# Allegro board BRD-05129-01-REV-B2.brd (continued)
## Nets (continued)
GTR_DP3_C2M_N_NC: JA1.D50
GTR_DP3_C2M_P_NC: JA1.D49
GTR_DP3_M2C_N_NC: JA1.C52
GTR_DP3_M2C_P_NC: JA1.C51
GTR_REFCLK0_C2M_N_NC: JA1.C48
GTR_REFCLK0_C2M_P_NC: JA1.C47
GTR_REFCLK1_C2M_N_NC: JA1.B50
GTR_REFCLK1_C2M_P_NC: JA1.B49
GTR_REFCLK2_C2M_N: JA1.D54 R495.1 U89.5
GTR_REFCLK2_C2M_P: JA1.D53 R495.2 U89.4
GTR_REFCLK3_C2M_N_NC: JA1.A52
GTR_REFCLK3_C2M_P_NC: JA1.A51
HDA00_CC: D21.1(CATHODE) J47.2 JA1.D16 R680.2
HDA01_NC: JA1.D17
HDA02: JA1.D18 R618.1
HDA03: JA1.B16 R627.1
HDA04: JA1.B17 R633.1
HDA05: JA1.B18 R620.1
HDA06: JA1.C18 U116.11 U117.11
HDA07: JA1.C19 U116.10 U117.13
HDA08_CC: JA1.C20 Q20.1 R261.1
HDA09_NC: JA1.A15
HDA10: JA1.A16 U116.13 U117.3
HDA11: JA1.A17 R276.1
HDA12: JA1.D20 R278.1
HDA13: JA1.D21 R280.1
HDA14: JA1.D22 R282.1
HDA15: JA1.B20 R277.1
HDA16_CC: JA1.B21 R279.1
HDA17: JA1.B22 R281.1
HDA18: JA1.C22 R283.1
HDA19_NC: JA1.C23
HDA20: JA1.C24 U121.6
HDA21: JA3.C10 R579.2 U100.6
HDA22: JA3.A10 R580.2 U100.5
HPA00_CCN: JA1.C4 U109.13
HPA00_CCP_CLK: JA1.C3 U109.15
HPA01N: JA1.D8 U111.15
HPA01P: JA1.D7 U109.12
HPA02N: JA1.D5 U111.13
HPA02P: JA1.D4 U111.14
HPA03N: JA1.C7 U109.14
HPA03P: JA1.C6 U111.12
HPA04N: JA1.B5 Q31.1 R567.1 R576.2 R590.1 U99.21
HPA04P: JA1.B4 Q32.1 R575.2 R589.1 U99.26
HPA05_CCN: JA1.B2 U99.1
HPA05_CCP: JA1.B1 U99.39
HPA06N: JA1.A4 U99.3
HPA06P: JA1.A3 U99.2
HPA07N: JA1.B8 U99.37
HPA07P_CLK: JA1.B7 U99.38
HPA08N: JA1.C10 R571.2 R585.1 U99.32
HPA08P: JA1.C9 R572.2 R586.1 U99.33
HPA09N: JA1.D11 R569.2 R583.1 U99.29
HPA09P: JA1.D10 R570.2 R584.1 U99.30
HPA10_CCN: JA1.C13 R563.2 U99.24
HPA10_CCP_CLK: JA1.C12 U99.23
HPA11N: JA1.B11 U19.2
HPA11P_CLK: JA1.B10 R477.2
HPA11P_CLK_R: R477.1 U91.3
HPA12N: JA1.A10 U115.13
HPA12P_CLK: JA1.A9 U115.15
HPA13N: JA1.A13 U115.14
HPA13P: JA1.A12 U115.12
HPA14N: JA1.D14 Q23.1 R474.1
HPA14P: JA1.D13 Q22.1 R473.1
HPA15_CCN: JA3.C2 U101.1
HPA15_CCP: JA3.C1 U101.39
HPA16N: JA3.A2 U101.37
HPA16P_CLK: JA3.A1 U101.38
HPA17N: JA3.D3 R597.2 R608.1 U101.35
HPA17P: JA3.D2 Q33.1 R596.1 R605.2 R616.1 U101.21
HPA18N: JA3.B3 R600.2 R611.1 U101.32
HPA18P: JA3.B2 R603.2 R612.1 U101.33
HPA19N: JA3.C5 R598.2 R609.1 U101.29
HPA19P: JA3.C4 R599.2 R610.1 U101.30
HPA20_CCN_NC: JA3.A5
HPA20_CCP_CLK: JA3.A4 R601.2 R614.1 U101.34
HPA21N_NC: JA3.D6
HPA21P_CLK: JA3.D5 R479.2
HPA21P_CLK_R: R479.1 U91.5
HPA22N: JA3.B6 R592.2 U101.24
HPA22P: JA3.B5 U101.23
HPA23N: JA3.C8 U118.4
HPA23P_CLK: JA3.C7 U120.5
HPA24N: JA3.A8 U101.3
HPA24P: JA3.A7 U101.2
HPA25: JA3.D8 U120.4
HPA26: JA3.D9 U118.5
HPA27: JA3.B8 Q34.1 R602.2 R615.1 U101.26
HPA28: JA3.B9 U19.3
HPA_CLK0N: JA1.A7 R568.2 R582.1 U99.35
HPA_CLK0P_CLK: JA1.A6 R574.2 R588.1 U99.34
I2C_SCK_LS: R55.2 U14.9 U15.6 U16.6 U19.8 U43.38
I2C_SDA_LS: R56.2 U14.8 U15.5 U16.5 U19.7 U43.39
JTAG_TCK_C2M: J3.6 JA1.A25 R66.2 R264.1
JTAG_TDI_C2M: J3.10 JA1.A24 U22.14
JTAG_TDO_M2C: J3.8 JA1.A23 U25.4
JTAG_TMS_C2M: J3.4 JA1.A22 U25.5
JTAG_VCCO_ON: R241.1 U22.8 U24.21
LS_OE_B: Q12.3 R233.2 U22.1 U25.2
MIO24_I2C_SCK: JA1.C26 U16.3
MIO25_I2C_SDA: JA1.C27 U16.4
MIO26: J1.1 JA1.D28 R45.2
MIO27_NC: JA1.D29
MIO28_NC: JA1.D30
MIO29_NC: JA1.C30
MIO30_NC: JA1.C31
MIO31: JA1.C32 R263.1 TP37.1(TP)
MIO32_NC: JA1.A31
MIO33_NC: JA1.A32
MIO34_NC: JA1.B38
MIO35: JA1.B28 R530.2 U13.7 U19.26
MIO36: JA1.B29 U64.4
MIO37: JA1.B30 U64.5
MIO38: JA1.B32 U98.38
MIO39: JA1.B33 U98.39
MIO40: JA1.B34 U98.1
MIO41: JA1.A34 U98.2
MIO42: JA1.A35 U98.3
MIO43: JA1.A36 U98.37
MIO44: JA1.D32 R547.2 R558.1 U98.34
MIO45: JA1.D33 R545.2 R556.1 U98.33
MIO46: JA1.D34 R544.2 R555.1 U98.32
MIO47: JA1.C34 R543.2 R554.1 U98.30
MIO48: JA1.C35 R542.2 R553.1 U98.29
MIO49: JA1.C36 R541.2 R552.1 U98.35
MIO50: JA1.B36 U98.23
MIO51: JA1.B37 R536.2 U98.24
MIO52: JA1.D36 U37.1
MIO53: JA1.D37 U37.31
MIO54: JA1.D38 U37.5
MIO55: JA1.C38 U37.2
MIO56: JA1.C39 U37.3
MIO57: JA1.C40 U37.4
MIO58: JA1.B40 U37.29
MIO59: JA1.B41 U37.6
MIO60: JA1.B42 U37.7
MIO61: JA1.A38 U37.9
MIO62: JA1.A39 U37.10
MIO63: JA1.A40 U37.13
MIO64_NC: JA1.D40
MIO65_NC: JA1.D41
MIO66: JA1.D42 U94.A4 U94.B4
MIO67: JA1.C42 U94.A1 U94.B1
MIO68: JA1.C43 U94.A8 U94.B8
MIO69_NC: JA1.C44
MIO70: JA1.B44 R683.2 U95.4
MIO71: JA1.B45 R682.1 U95.2
MIO72: JA1.B46 R681.1 U95.3 U95.5
MIO73_NC: JA1.A42
MIO74_NC: JA1.A43
MIO75_NC: JA1.A44
MIO76: JA1.D44 U19.4
MIO77: JA1.D45 U19.22
MODE0_C2M: JA1.A27 R165.1 TP65.1(TP)
MODE1_C2M: JA1.A28 R164.1 TP64.1(TP)
MODE2_C2M: JA1.A29 R163.1 TP63.1(TP)
MODE3_C2M: JA1.A30 R162.1 TP62.1(TP)
MOTOR_CS_B_R: R756.2 R758.2 R760.2 U109.7
MOTOR_PA_CRNT: C723.1 J52.1(P1) R61.1 R646.2
MOTOR_PA_CS_B: R756.1 U108.10
MOTOR_PA_CURRENT+: C813.1 R740.2 U108.8
MOTOR_PA_CURRENT-: C812.1 R741.2 U108.7(VINB-)
MOTOR_PA_DATAA: U108.14 U109.8
MOTOR_PA_DATAB: U108.13 U109.9
MOTOR_PA_HS: C688.2 J27.1(P1) Q35.1 Q35.2 Q35.3(S3) Q36.5 R638.1 U102.4 U105.8
MOTOR_PA_I: R646.1 U105.5
MOTOR_PA_OUT: J32.1 R638.2 R641.1 U105.1
MOTOR_PA_R_V+: R702.2 R738.1 U127.4
MOTOR_PA_R_V-: R703.2 R739.1 U127.5
MOTOR_PA_SCLK: R755.1 U108.15
MOTOR_PA_VOCM: C711.1 U105.3 U105.7 U123.6 U123.7(OUT) U127.2(VOCM) U128.2(VOCM)
MOTOR_PA_VOCM2: R58.1 R63.1 U123.1 U123.2
MOTOR_PA_VOLT: R64.1 U135.1 U135.2
MOTOR_PA_VOLTAGE+: C811.1 R738.2 U108.1
MOTOR_PA_VOLTAGE-: C810.1 R739.2 U108.2
MOTOR_PB_CRNT: C734.1 J53.1(P1) R650.2 R712.1
MOTOR_PB_CS_B: R758.1 U110.10
MOTOR_PB_CURRENT+: C817.1 R744.2 U110.8
MOTOR_PB_CURRENT-: C816.1 R745.2 U110.7(VINB-)
MOTOR_PB_DATAA: U110.14 U111.6
MOTOR_PB_DATAB: U110.13 U111.7
MOTOR_PB_HS: C696.2 J29.1(P1) Q38.1 Q38.2 Q38.3(S3) Q39.5 R639.1 U103.4 U106.8
MOTOR_PB_I: R650.1 U106.5
MOTOR_PB_OUT: J32.2 R639.2 R647.1 U106.1
MOTOR_PB_SCLK: R757.1 U110.15
MOTOR_PB_VOCM: C713.1 U106.3 U106.7 U124.6 U124.7(OUT) U129.2(VOCM) U130.2(VOCM)
MOTOR_PB_VOCM2: R707.1 R711.1 U124.1 U124.2
MOTOR_PB_VOLT: R708.1 U136.6 U136.7(OUT)
MOTOR_PB_VOLTAGE+: C815.1 R742.2 U110.1
MOTOR_PB_VOLTAGE-: C814.1 R743.2 U110.2
MOTOR_PC_CRNT: C743.1 J54.1(P1) R656.2 R720.1
MOTOR_PC_CS_B: R760.1 U112.10
MOTOR_PC_CURRENT+: C821.1 R748.2 U112.8
MOTOR_PC_CURRENT-: C820.1 R749.2 U112.7(VINB-)
MOTOR_PC_DATAA: U111.8 U112.14
MOTOR_PC_DATAB: U111.9 U112.13
MOTOR_PC_HS: C703.2 J31.1(P1) Q40.1 Q40.2 Q40.3(S3) Q41.5 R640.1 U104.4 U107.8
MOTOR_PC_I: R656.1 U107.5
MOTOR_PC_OUT: J32.3 R640.2 R651.1 U107.1
MOTOR_PC_SCLK: R759.1 U112.15
MOTOR_PC_VOCM: C715.1 U107.3 U107.7 U125.6 U125.7(OUT) U131.2(VOCM) U132.2(VOCM)
MOTOR_PC_VOCM2: R715.1 R719.1 U125.1 U125.2
MOTOR_PC_VOLT: R716.1 U136.1 U136.2
MOTOR_PC_VOLTAGE+: C819.1 R746.2 U112.1
MOTOR_PC_VOLTAGE-: C818.1 R747.2 U112.2
MOTOR_SCLK_R: R755.2 R757.2 R759.2 U109.6
MP5016_DVDT: C206.1 U41.10
MP5016_EN: R133.2 U41.9
MP5016_GATE: C234.1 Q5.3 U41.8
MP5016_ILIMIT: R135.1 U41.4
MP5016_MODE: C235.1 R134.1 U41.5
OSC_25M_CLK: R501.2 U91.1
OSC_25M_CLK_R: R501.1 U92.3
OSC_25M_OE: R500.2 U92.1
OSC_26M_OE: R494.2 U89.1
PA_HB: C688.1 D3.1(CATHODE) U102.2
PA_HO: R619.1 U102.3
PA_HOG: Q35.4 R619.2
PA_LO: R621.1 U102.10
PA_LOG: Q36.4 R621.2
PA_RDT: R625.1 U102.6
PB_HB: C696.1 D4.1(CATHODE) U103.2
PB_HO: R628.1 U103.3
PB_HOG: Q38.4 R628.2
PB_LO: R629.1 U103.10
PB_LOG: Q39.4 R629.2
PB_RDT: R631.1 U103.6
PC4_CON_PGND: J3.13 Q12.1 Q13.3 R234.2
PC_HB: C703.1 D5.1(CATHODE) U104.2
PC_HO: R634.1 U104.3
PC_HOG: Q40.4 R634.2
PC_LO: R635.1 U104.10
PC_LOG: Q41.4 R635.2
PC_RDT: R637.1 U104.6
PL_1V8: C7.1 C8.1 C582.1 C591.1 C592.1 C645.1 C646.1 C647.1 C654.1 C655.1 C656.1 C657.1 C667.1 C668.1 C669.1 C676.1 C677.1 C678.1 C679.1 C719.1 C733.1 C755.1 C769.1 C778.1 JA1.D1 JA1.D2 R14.1 R446.1 R500.1 R507.1 R563.1 R564.1 R568.1 R569.1 R570.1 R571.1 R572.1 R573.1 R574.1 R575.1 R592.1 R593.1 R597.1 R598.1 R599.1 R600.1 R601.1 R602.1 R603.1 R604.1 TP10.1(TP) TP56.1(TP) U3.5-6 U3.12 U91.6 U92.4(VDD) U99.25 U99.31 U99.40 U101.25 U101.31 U101.40 U109.2(VCCB) U111.2(VCCB) U115.2(VCCB) U118.6(VCCB) U120.6(VCCB)
PL_1V8_FB: R14.2 R16.1 U3.10
PL_2V5: C21.1 C22.1 C716.1 C717.1 C727.1 C728.1 C740.1 C741.1 C752.1 C753.1 R24.1 TP11.1(TP) TP57.1(TP) U9.1 U108.9 U110.9 U112.9 U114.9
PL_2V5_EN: C829.1 R472.2 U9.5
PL_2V5_FB: C21.2 R23.1 R24.2 U9.4
PL_3V3: C23.1 C29.1 C237.1 C581.1 C614.1 C615.1 C666.1 C710.1 C712.1 C714.1 C718.1 C720.1 C721.1 C729.1 C730.1 C732.1 C738.1 C739.1 C747.1 C754.1 C756.1 C757.1 C764.1 C766.1 C768.1 C773.1 C777.1 C785.1 C789.1 C793.1 C794.1 C795.1 C796.1 C797.1 C798.1 C799.1 C800.1 C801.1 C802.1 C803.1 C804.1 C805.1 J25.P11_L2_U J25.P11_L4_L J25.P14_L1_U J25.P14_L3_L J47.1 JA1.B13 JA1.B14 L16.1 L17.1 R166.1 R471.1 R472.1 R524.1 R565.1 R576.1 R579.1 R580.1 R594.1 R605.1 R622.1 R672.1 R680.1 TP12.1(TP) TP58.1(TP) U8.8 U9.8 U42.5 U97.5-6 U97.12 U100.2 U100.8 U105.6(VS) U106.6(VS) U107.6(VS) U108.16 U109.3 U109.5 U110.16 U111.3 U111.4 U111.5 U112.16 U113.6(VS) U114.16 U115.3 U115.5 U116.14(VCCB) U117.6 U117.16(VCC) U118.7 U118.10 U119.14 U120.7 U123.8 U124.8 U125.8 U127.3 U127.7 U128.3 U128.7 U129.3 U129.7 U130.3 U130.7 U131.3 U131.7 U132.3 U132.7 U133.3 U133.7 U134.3 U134.7 U135.8 U136.8 U137.8
PL_3V3_FB: R524.2 R525.1 U97.10
PL_4V5_TRQ: C770.1 C771.1 C772.1 C780.1 C787.1 C788.1 J45.1 R673.1 R684.1 TP13.1(TP) TP59.1(TP) U119.13 U122.1
PL_4V5_TRQ_FB: C788.2 R684.2 R685.1 U122.4
PL_5V0: C618.1 C763.1 C765.1 C767.1 J42.4 J43.7 J43.8 Q25.3 R664.1 R665.1 R666.1 R667.1 TP14.1(TP) TP60.1(TP) U116.1
PL_12V0: C617.1 C692.1 C693.1 C700.1 C701.1 C707.1 C708.1 C783.1 Q24.3 R617.1 R626.1 R632.1 TP15.1(TP) TP61.1(TP) U102.1 U103.1 U104.1 U121.4(VDD)
PL_ETH_0V9: C27.1 C28.1 C650.1 C651.1 C652.1 C653.1 C661.1 C662.1 C663.1 C672.1 C673.1 C674.1 C675.1 C683.1 C684.1 C685.1 R27.1 TP9.1(TP) TP55.1(TP) U8.1 U99.4 U99.28 U99.36 U101.4 U101.28 U101.36
PL_ETH_0V9_EN: C828.1 R471.2 U8.5
PL_ETH_0V9_FB: C27.2 R27.2 R29.1 U8.4
PL_GEM1_LED1_LS: J25.P13_L1_U R577.2
PL_GEM1_LED2_LS: J25.P12_L2_U R578.2
PL_GEM1_MDI_0_N: J25.P1_U U99.13
PL_GEM1_MDI_0_P: J25.P2_U U99.12
PL_GEM1_MDI_1_N: J25.P3_U U99.15
PL_GEM1_MDI_1_P: J25.P4_U U99.14
PL_GEM1_MDI_2_N: J25.P5_U U99.17
PL_GEM1_MDI_2_P: J25.P6_U U99.16
PL_GEM1_MDI_3_N: J25.P7_U U99.19
PL_GEM1_MDI_3_P: J25.P8_U U99.18
PL_GEM1_MDIX_MODE: R573.2 R587.1 U99.27
PL_GEM1_RESET_B: R565.2 U19.12 U99.7
PL_GEM2_LED3_LS: J25.P13_L3_L R606.2
PL_GEM2_LED4_LS: J25.P12_L4_L R607.2
PL_GEM2_MDI_0_N: J25.P1_L U101.13
PL_GEM2_MDI_0_P: J25.P2_L U101.12
PL_GEM2_MDI_1_N: J25.P3_L U101.15
PL_GEM2_MDI_1_P: J25.P4_L U101.14
PL_GEM2_MDI_2_N: J25.P5_L U101.17
PL_GEM2_MDI_2_P: J25.P6_L U101.16
PL_GEM2_MDI_3_N: J25.P7_L U101.19
PL_GEM2_MDI_3_P: J25.P8_L U101.18
PL_GEM2_MDIX_MODE: R604.2 R613.1 U101.27
PL_GEM2_RESET_B: R594.2 U19.13 U101.7
PL_RESET_OUT3_B_NC: U19.17
PMOD1_IO1_HDA11: C372.1 J2.1 R274.2 R276.2
PMOD1_IO2_HDA12: C374.1 J2.3 R278.2
PMOD1_IO3_HDA13: C377.1 J2.5 R280.2
PMOD1_IO4_HDA14: C379.1 J2.7 R282.2
PMOD1_IO5_HDA15: C373.1 J2.2 R275.2 R277.2
PMOD1_IO6_HDA16_CC: C375.1 J2.4 R279.2
PMOD1_IO7_HDA17: C378.1 J2.6 R281.2
PMOD1_IO8_HDA18: C380.1 J2.8 R283.2
PMOD_3V3: C238.1 C376.1 C387.1 J2.11 J2.12 U42.1(OUT)
PMOD_PWR_EN: R167.1 U42.4
PMOD_PWR_FLT_B: R166.2 U42.3
PMU_RESET_OUT_B: J51.2(P2) U19.16
PS_1V2: C24.1 C25.1 C283.1 C284.1 C285.1 C286.1 C289.1 C290.1 C291.1 C292.1 C295.1 C296.1 R21.1 TP5.1(TP) TP51.1(TP) U5.5-6 U5.12 U43.5 U43.12 U43.15 U43.21 U43.28 U43.33 U43.43 U43.49
PS_1V2_FB: R21.2 R26.1 U5.10
PS_1V8: C50.1 C81.1 C91.1 C92.1 C275.1 C276.1 C277.1 C329.1 C600.1 C612.1 C613.1 C622.1 C623.1 C624.1 C631.1 C632.1 C633.1 C640.1 J3.2 L10.1 R45.1 R46.1 R47.1 R48.1 R49.1 R210.1 R447.1 R448.1 R449.1 R450.1 R451.1 R515.1 R516.1 R522.1 R530.1 R536.1 R537.1 R541.1 R542.1 R543.1 R544.1 R545.1 R546.1 R547.1 R548.1 R683.1 TP6.1(TP) TP52.1(TP) U13.1 U13.10 U16.2 U22.2(VCCB) U22.12 U22.13 U25.6(VCCB) U37.8 U37.11 U37.14 U37.28 U37.30 U37.32 U64.6(VCCB) U94.A5 U94.B5 U96.1 U98.25 U98.31 U98.40
PS_1V8_EN: R521.2 U96.5
PS_1V8_FB: C612.2 R522.2 R523.1 U96.4
PS_1V8_RS485: C602.1 L10.2 R519.1 U95.1
PS_3V3: C1.1 C2.1 C5.1 C17.1 C53.1 C64.1 C176.1 C297.1 C298.1 C299.1 C300.1 C303.1 C304.1 C559.1 C560.1 C561.1 C574.1 C589.1 C611.1 J24.11 J24.13 L15.1 R1.1 R54.1 R55.1 R56.1 R130.1 R218.1 R220.2 R243.1 R256.2 R429.1 R463.1 R464.1 R468.2 R469.2 R494.1 R521.1 R538.1 R549.1 TP7.1(TP) TP53.1(TP) U1.7-9 U12.8 U15.1 U15.8 U38.6 U38.14 U38.22 U38.36 U43.16 U43.31 U43.37 U43.44 U43.55 U89.6(VCC) U96.8
PS_3V3_FB: R1.2 R2.1 U1.10
PS_3V3_MODE: R4.2 R5.1 U1.13
PS_3V3_RAMP: C5.2 U1.11
PS_ERROR_OUT_M2C: JA1.B24 TP38.1(TP)
PS_ERROR_STATUS_M2C: JA1.B25 TP39.1(TP)
PS_ETH_0V9: C14.1 C16.1 C627.1 C628.1 C629.1 C630.1 C636.1 C637.1 C638.1 R6.1 TP8.1(TP) TP54.1(TP) U12.1 U98.4 U98.28 U98.36
PS_ETH_0V9_EN: R243.2 U12.5
PS_ETH_0V9_FB: C14.2 R6.2 R17.1 U12.4
PS_GEM0_LED0_CA: J24.12 R561.2
PS_GEM0_LED1_CA: J24.14(YLW_CA) R551.2
PS_GEM0_MDI_0_N: J24.2 U98.13
PS_GEM0_MDI_0_P: J24.1 U98.12
PS_GEM0_MDI_1_N: J24.6 U98.15
PS_GEM0_MDI_1_P: J24.3 U98.14
PS_GEM0_MDI_2_N: J24.5 U98.17
PS_GEM0_MDI_2_P: J24.4 U98.16
PS_GEM0_MDI_3_N: J24.8 U98.19
PS_GEM0_MDI_3_P: J24.7 U98.18
PS_GEM0_MDIX_MODE: R546.2 R557.1 U98.27
PS_GEM0_PHY_CFG0: Q29.1 R549.2 R550.1 R560.1 U98.21
PS_GEM0_PHY_CFG1: Q30.1 R548.2 R559.1 U98.26
PS_GEM0_RESET_B: R538.2 U19.29 U98.7
PS_GEM0_XTAL_IN: C644.1 R540.2 U98.9 X14.3(X3)
PS_GEM0_XTAL_OUT: C643.1 R540.1 U98.8(XTAL_O) X14.1
PS_POR_B: J51.1 JA1.C15 Q45.3 U19.11
PS_RESET_OUT2_B_NC: U19.19
PS_RESET_OUT5_B_NC: U19.32
PS_RESET_OUT6_B_NC: U19.10
PS_SRST_C2M_B: J1.3(P3) J3.14 JA1.C16 Q47.3
PWRGD_FPD_M2C: JA1.D24 Q7.1
PWRGD_LPD_M2C: JA1.D25 Q17.1
PWRGD_PL_M2C: JA1.D26 Q9.1
PWROFF_C2M_B: C207.1 J12.3(PLUG DET) JA1.B26 Q6.1 Q21.3 U7.3(PG)
QEI_DP_A_N: D18.2(CATHODE2) J43.5 R669.2 U117.9
QEI_DP_A_P: D18.1 J43.6 R669.1 U117.10
QEI_DP_B_N: D17.2(CATHODE2) J43.9(P9) R670.2 U117.15
QEI_DP_B_P: D17.1 J43.10 R670.1 U117.14
QEI_DP_I_N: D19.2(CATHODE2) J43.3 R671.2 U117.1
QEI_DP_I_P: D19.1 J43.4 R671.1 U117.2
QEI_LOW_REF: R667.2 R668.1 U117.7
QEI_SE_A: D16.2(CATHODE2) J42.3 R665.2 U116.4
QEI_SE_B: D15.2(CATHODE2) J42.5 R666.2 U116.5
QEI_SE_I: D16.1 J42.2 R664.2 U116.2
QEI_SEL: J44.1 R672.2 U116.8 U117.12
SD_CTRLR_RESET_B: R429.2 U19.18 U38.18
SDIO_CD_B: J11.13 R130.2 U38.26
SDIO_CLK: R249.1 U38.9
SDIO_CLK_R: J11.5 R249.2 U82.7
SDIO_CMD: R248.1 U38.11
SDIO_CMD_R: J11.3 R248.2 U82.6
SDIO_DATA0: R250.1 U38.5
SDIO_DATA0_R: J11.7 R250.2 U82.1
SDIO_DATA1: R251.1 U38.4
SDIO_DATA1_R: J11.8 R251.2 U82.2
SDIO_DATA2: R252.1 U38.25
SDIO_DATA2_R: J11.1 R252.2 U82.3
SDIO_DATA3: R253.1 U38.23
SDIO_DATA3_R: J11.2 R253.2 U82.5
SDIO_SCK: R464.2 U38.31
SDIO_SDA: R463.2 U38.27
SDIO_VDD: C369.1 C557.1 C558.1 C565.1 J11.4 R462.1 U38.21 U82.8(VCC)
SDIO_VDD18: C175.1 U38.13
SDIO_VDD18PLL: C562.1 U38.34
SDIO_WP: R465.1 U38.30
SDIO_XTAL1: C563.1 R466.1 U38.33 X11.3(X3)
SDIO_XTAL2: C564.1 R466.2 U38.32(XTAL2) X11.1
SOM240_1_C45_NC: JA1.C45
SOM240_1_D46_NC: JA1.D46
SOM_5V0: C323.1 C324.1 C353.1 C354.1 JA1.A59 JA1.A60 JA1.B60 JA1.C59 JA1.C60 JA1.D60 U14.14 U14.15 U14.16
TRQ_CS_B: U119.3 U120.9
TRQ_REFIN_N: C774.2 C776.1 R674.2 R675.2 U119.10
TRQ_REFIN_P: C774.1 C775.1 R673.2 R674.1 U119.9
TRQ_SCLK: U119.1(SCLK) U120.8
TRQ_SDI: U118.9 U119.16
TRQ_SDO: U118.8 U119.15
TRQ_SNS_N: D20.2(CATHODE2) J45.4(P4) R677.1
TRQ_SNS_P: D20.1 J45.3 R676.1
TRQ_SNS_R_N: C779.2 C782.1 R677.2 U119.6
TRQ_SNS_R_P: C779.1 C781.1 R676.2 U119.5
TS_CLK: TP40.1(TP) U119.2
USB0_ATEST: R222.1 U43.52
USB0_CFG_BC_EN: R219.1 U43.40
USB0_CFG_NON_REM: R220.1 U43.41
USB0_D1_N: U38.3 U43.2
USB0_D1_P: U38.2 U43.1
USB0_D2_N: U43.9 U44.11 X6.1
USB0_D2_P: U43.8 U44.12 X6.2
USB0_D3_N: U43.18 U44.2 X5.1
USB0_D3_P: U43.17 U44.3 X5.2
USB0_HUB_RESET_B: R218.2 U19.1 U43.42
USB0_PHY_RESET_B: R210.2 U19.28 U37.27
USB0_PRT_CTL1_NC: U43.36
USB0_PRT_CTL2: U43.35 U45.3 U45.8
USB0_PRT_CTL3: U43.34 U45.4 U45.5
USB0_RBIAS: R221.1 U43.56
USB0_SSRX2_N: U43.14 U44.14 U66.1 U66.10(NC4)
USB0_SSRX2_P: U43.13 U44.15 U66.2 U66.9
USB0_SSRX3_N: U43.23 U44.5 U66.4 U66.7
USB0_SSRX3_P: U43.22 U44.6 U66.5 U66.6
USB0_SSTX2_C_N: C280.1 U44.17 U67.4 U67.7
USB0_SSTX2_C_P: C282.1 U44.18 U67.5 U67.6
USB0_SSTX2_N: C280.2 U43.11
USB0_SSTX2_P: C282.2 U43.10
USB0_SSTX3_C_N: C279.2 U44.8 U67.1 U67.10(NC4)
USB0_SSTX3_C_P: C281.2 U44.9 U67.2 U67.9
USB0_SSTX3_N: C279.1 U43.20
USB0_SSTX3_P: C281.1 U43.19
USB0_USB3320_D_N: U37.19 U43.46
USB0_USB3320_D_P: U37.18 U43.45
USB0_VBUS2: C274.1 U44.10(U_VBUS) U45.7 X6.6(VBUS)
USB0_VBUS3: C272.1 U44.1 U45.6(OUT2) X5.6(VBUS)
USB_JTAG_DM_N: J4.2 U24.7 X1.2
USB_JTAG_DM_P: J4.3 U24.8 X1.1
USB_JTAG_FLTR: C78.1 C87.1 C89.1 L4.1 R40.1 U11.5 U11.8
USB_JTAG_VBUS: C88.1 J4.1(VBUS) L4.2 X1.6(VBUS)
USB_JTAG_VCORE: C95.1 C96.1 C97.1 C98.1 U24.12 U24.37 U24.49(VREGOUT) U24.64
USB_JTAG_VPHY: C82.1 C83.1 L2.2 U24.4
USB_JTAG_VPLL: C84.1 C85.1 L3.2 U24.9
USB_PWRD_VCCIO: C44.1 C79.1 C80.1 C90.1 C93.1 C94.1 C99.1 C100.1 C101.1 C102.1 C105.1 D24.1(CATHODE) D25.1(CATHODE) L2.1 L3.1 R36.1 R74.1 R75.1 R76.1 R77.1 R233.1 R234.1 R235.1 R266.1 R267.1 R764.1 R765.1 U11.1 U22.3 U22.4 U24.20 U24.31 U24.42 U24.50 U24.56 U25.7 U25.10 U26.8 U64.7 U64.10
UTIL_3V3: C41.1 C42.1 C49.1 DS1.2 DS2.2 DS3.2 DS4.2 DS5.2 DS6.2 DS7.2 DS8.2 DS9.2 R39.1 R260.1 TP4.1(TP) TP50.1(TP) U7.1 U14.10(VS)
VISOIN_RS485: C603.1 C604.1 L12.2 U95.16
VISOOUT_RS485: C608.1 C609.1 C610.1 L12.1 R534.2 U95.12
VREF_DCLINK: C760.1 C761.1 C762.1 R736.2 U114.3 U114.6
VREF_PA: C724.1 C725.1 C726.1 R730.2 U108.3 U108.6
VREF_PA_R: C806.1 R730.1 R731.2 U123.3 U123.5
VREF_PB: C735.1 C736.1 C737.1 R732.2 U110.3 U110.6
VREF_PB_R: C807.1 R732.1 R733.2 U124.3 U124.5
VREF_PC: C744.1 C745.1 C746.1 R734.2 U112.3 U112.6
VREF_PC_R: C808.1 R734.1 R735.2 U125.3 U125.5
WATCHDOG_CRST: C52.1 R49.2 U13.4
WATCHDOG_CWD: C51.1 R48.2 U13.2
WATCHDOG_SET0: R47.2 R51.1 U13.3
WATCHDOG_SET1: R46.2 R50.1 U13.6
WATCHDOG_WDO_B: J1.2 U13.8(WDO_B)
Y_RS485: D23.2(CATHODE2) J22.4(P4) U95.17
Z_RS485: D23.1 J22.3 U95.18(Z)
N1366089: C208.2 D2.2 L9.2 Q18.3
N1766802: R33.1 U6.2
N1766806: C37.1 R33.2
N1766990: Q21.2(SOURCE) R265.2 U6.7
N1767106: C39.2 R30.2 R31.1 R32.2
N1767370: C319.2 R223.1
N2390901: Q18.1 Q20.3 R260.2
N2549814: C344.1 R264.2
N3548094: R428.1 U38.35
N3957555: R213.1 U37.24
N3957585: R209.2 U37.22
N3957595: C278.2 U37.20
N3957977: C568.1 U43.54 X13.1
N3957979: C569.1 U43.53(XTALO) X13.3(X2)
N3958007: R468.1 U43.24
N3958011: R469.1 U43.25
N3958031: C566.1 R467.1 U37.26 X12.3(X3)
N3958033: C567.1 R467.2 U37.25(XO) X12.1
N5304511: C642.1 J24.9
N5304817: R537.2 U98.22
N5305693: Q30.3 R561.1
N5305711: R539.1 U98.10
N5322338: C665.1 J25.P9_U(TRCT1/2/3/4_U)
N5322486: R564.2 U99.22
N5323316: R566.1 U99.10
N5323550: Q32.3 R578.1
N5323954: Q31.3 R567.2 R577.1
N5327477: C687.1 J25.P9_L
N5327617: R593.2 U101.22
N5328445: R595.1 U101.10
N5328687: Q34.3 R607.1
N5371142: Q29.3 R550.2 R551.1
N5372640: Q33.3 R596.2 R606.1
N5400806: J21.2 R520.1
N5403476: J19.2 R517.1
N5403484: J20.2 R518.1
N5403540: C601.1 R517.2 R518.2
N15688918: DS10.2 R622.2
N15743132: R581.1 U100.7(WC_B)
N15988053: Q28.1 R531.2 R532.1
N15988135: Q28.3 R533.1
N15988139: DS9.1 R533.2
N15991161: J23.1 R164.2
N15992386: J40.1(P1) Q44.3 R660.2 R661.1 R662.1
N15992390: J41.1(P1) R663.1 U113.5
N15992479: C695.1 J26.1(P1) R618.2 R624.1 U102.8
N15992497: C702.1 J28.1(P1) R627.2 R630.1 U103.8
N15992515: C709.1 J30.1(P1) R633.2 R636.1 U104.8
N16064973: R526.2 R528.1 R754.1
N16065039: C619.1 Q24.1 R528.2
N16065865: Q27.3 R527.2 R529.1
N16065931: C620.1 Q25.1 R529.2
N16074030: R451.2 U19.5
N16074034: R450.2 U19.6
N16074038: R449.2 U19.9
N16074042: R448.2 U19.20
N16074046: R447.2 U19.21
N16074090: R446.2 U19.27
N16074170: R507.2 U91.2
N16074248: C73.1 R54.2 U16.7(VREF2) U16.8
N16077585: Q22.3 R294.1
N16077589: DS7.1 R294.2
N16077723: Q23.3 R295.1
N16077727: DS8.1 R295.2
N16080552: Q6.3 R157.1
N16080556: DS1.1 R157.2
N16080656: Q17.3 R254.1
N16080660: DS6.1 R254.2
N16080760: Q7.3 R158.1
N16080764: DS2.1 R158.2
N16080864: Q8.3 R159.1
N16080868: DS3.1 R159.2
N16080968: Q9.3 R160.1
N16080972: DS4.1 R160.2
N16081072: Q10.3 R161.1
N16081076: DS5.1 R161.2
N16081750: R66.1 U22.15
N16081820: J4.4 X1.3
N16081954: C88.2 J4.5 L5.2
N16082016: R75.2 U24.14
N16082024: R74.2 R78.1 U26.4
N16082026: R76.2 U24.62 U26.2
N16082028: R77.2 U24.63 U26.1
N16082050: R78.2 U24.61 U26.3
N16082060: C103.1 U24.2 X2.1
N16082074: C104.1 U24.3 X2.3(X3)
N16082098: R79.2 U24.6
N16087534: C370.1 R274.1
N16087546: C371.1 R275.1
N16095299: R534.1 U95.13
N16189579: D3.2 R617.2
N16189629: D4.2 R626.2
N16189705: D5.2 R632.2
N16192308: C694.1 Q37.1 R620.2 R623.1 U102.7 U103.7 U104.7
N16238907: R519.2 U95.8
N17003721: R641.2 R642.1 R643.1 TP41.1(TP)
N17003765: C722.1 R643.2 U135.3
N17003879: R647.2 R648.1 R649.1 TP43.1(TP)
N17003923: C731.1 R649.2 U136.5
N17004020: R651.2 R652.1 R653.1 TP45.1(TP)
N17004081: C742.1 R653.2 U136.3
N17015726: R63.2 R702.1 U127.1
N17015844: R64.2 R703.1 U127.8
N17015909: R58.2 R704.1 U128.1
N17015913: R704.2 R740.1 U128.4
N17016027: R61.2 R705.1 U128.8
N17016033: R705.2 R741.1 U128.5
N17019057: R706.1 R707.2 U129.1
N17019061: R706.2 R742.1 U129.4
N17019189: R708.2 R709.1 U129.8
N17019195: R709.2 R743.1 U129.5
N17019244: R710.1 R711.2 U130.1
N17019248: R710.2 R744.1 U130.4
N17019376: R712.2 R713.1 U130.8
N17019382: R713.2 R745.1 U130.5
N17020691: R714.1 R715.2 U131.1
N17020695: R714.2 R746.1 U131.4
N17020826: R716.2 R717.1 U131.8
N17020832: R717.2 R747.1 U131.5
N17020881: R718.1 R719.2 U132.1
N17020885: R718.2 R748.1 U132.4
N17021016: R720.2 R721.1 U132.8
N17021022: R721.2 R749.1 U132.5
N17021071: R722.1 R723.2 U133.1
N17021075: R722.2 R750.1 U133.4
N17021203: R724.2 R725.1 U133.8
N17021209: R725.2 R751.1 U133.5
N17021264: R726.1 R727.2 U134.1
N17021268: R726.2 R752.1 U134.4
N17021396: R728.2 R729.1 U134.8
N17021402: R729.2 R753.1 U134.5
N17049267: C758.1 R662.2 U135.5
N17065894: C809.1 R736.1 R737.2 U137.3 U137.5
N17098770: DS10.1 Q37.3
N17140493: Q26.3 R754.2
N17244604: Q43.3 Q44.1 R762.2 R763.1
N17444223: C826.1 D24.2 Q45.1 Q46.3 R267.2
N17444428: C827.1 D25.2 Q47.1 Q48.3 R764.2

Pads without a net: D15 1; F1 2 4; J3 12; J19 3; J20 3; J21 3; J44 3; U1 4-6 16 19 20; U3 3-4; U5 3-4; U6 1 15; U7 2 7; U8 2 7; U9 2 7; U11 2 7; U12 2 7; U13 9; U14 7 13; U22 9; U24 28 29 30 32 33 34 36 38 39 40 41 43 44 45 46 48 53 54 55 57 58 59 60; U26 6 7; U37 12 15 16 17; U38 1 7 8 10 12 15 16 17 19 20 24 29; U43 3 4 6 7 26 27 29 30 32; U89 2; U94 A11 B11; U95 7; U96 2 7; U97 3-4; U98 6; U99 6 8; U101 6 8; U102 5; U103 5; U104 5; U116 6 9 12; U117 5; U119 4 7 8 11; U122 2 7; X1 5; X5 3 5; X6 3 5

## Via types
v1: diameter 0.483, hole 0.249, TOP to BOTTOM, 1871 vias
v2: diameter 0.61, hole 0.305, TOP to BOTTOM, 11 vias
v3: diameter 0.457, hole 0.254, TOP to L03_SIG, 191 vias
v4: diameter 0.406, hole 0.18, TOP to BOTTOM, 221 vias
v5: diameter 0.457, hole 0.254, L12_SIG to BOTTOM, 40 vias
v6: diameter 0.5, hole 0.203, TOP to BOTTOM, 27 vias
v7: diameter 0.457, hole 0.203, TOP to BOTTOM, 82 vias
v8: diameter 0.508, hole 0.249, TOP to BOTTOM, 289 vias
v9: diameter 0.406, hole 0.203, TOP to BOTTOM, 40 vias
v10: diameter 0.5, hole 0.249, TOP to BOTTOM, 34 vias
v11: diameter 0.6, hole 0.305, TOP to BOTTOM, 20 vias

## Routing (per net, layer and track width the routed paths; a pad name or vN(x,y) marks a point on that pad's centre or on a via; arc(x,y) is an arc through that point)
5V0_IN: length 24.8
  TOP w0.254: U94.B10 111.06,103.04 110.94,103.16 v1(110.92,103.16) ; U94.B3 109.85,104.04 v1(109.99,103.9)
  TOP w0.381: v1(106.11,105.14) 106.44,104.81 U94.A3 ; U94.A10 v1(114.69,102.27)
  BOTTOM w0.203: U19.31 36.38,40.67 36.92,40.12 v1(36.92,39.87) ; U19.15 31.81,42.67 v1(31.39,43.09) ; U3.7 35.76,80.72
  BOTTOM w0.254: v1(39.3,44.2) 39.07,43.97 R28.1 ; v1(39.64,91.27) 39.87,91.49 U45.2 ; v1(36.92,39.87) 37.66,39.87 C75.1 ; v1(39.21,45.23) 38.93,44.95 R7.1 ; U37.21 v1(46.88,76.71) ; C35.1 25.59,28.17
  BOTTOM w0.381: 6.53,50.92 R4.1 ; R4.1 5.98,51.48 ; R4.1 6.53,52.04 ; U14.1 v8(6.24,72.87) ; v1(106.11,105.14) 106.15,105.18 C599.1 ; U14.3 v8(4.94,72.87) ; 124.7,70.61 R527.1 124.14,70.05 ; R30.1 v8(16.57,17.96) ; C39.1 v8(17.59,17.96) ; R209.1 v1(50.03,75.69) ; C273.1 v1(48.43,76.63) ; C598.1 110.99,103.23 v1(110.92,103.16) ; v8(4.11,76.12) 3.64,76.59 U14.12 ; U14.2 v8(5.59,72.87)
  vias: v1(5.36,50.74) v1(5.36,49.6) v1(5.48,51.89) v1(6.5,50.74) v1(6.5,49.6) v1(28.07,78.87) v1(28.07,77.85) v1(28.38,82.77) v1(30.22,80.73) v1(31.24,80.73) v1(35.66,79.78) v1(41.34,92.74) v1(42.69,91.74) v1(64.68,24.3) v1(65.82,24.3) v1(68.8,23.82) v1(69.97,18.36) v1(70.73,18.99) v1(70.73,17.72) v1(112.75,88.57) v1(113.56,89.43) v1(123.63,70.09) v1(123.68,71.99) v1(123.68,71.1) v2(26.97,27.61) v6(20.11,26.39) v6(20.51,28.44) v6(20.51,27.42) v6(21.31,26.54) v6(22.32,26.54) v6(22.54,28.44) v6(22.54,27.42) v6(23.34,26.54) v6(24.35,26.54) v6(24.57,28.44) v6(24.57,27.42) v6(25.37,26.54) v8(4.94,73.88) v8(5.59,73.88) v8(6.09,46.33) v8(6.24,73.88) v8(9.61,46.21) v8(9.61,45.32)
5V0_IN_EN: length 3.6
  BOTTOM w0.203: U6.3 17.99,21.81 18.6,21.21 R34.2
5V0_IN_FB: length 2.4
  BOTTOM w0.203: U6.4 17.59,21.58 18.04,21.13 R32.1
5V0_IN_SS: length 2.1
  BOTTOM w0.203: C40.1 15.75,20.94 16.79,21.98 U6.6
5V0_IN_SW: length 1.7
  BOTTOM w0.381: 20.71,19.49 C37.2 21.27,20.04 ; C319.1 22.29,20.04
5V0_IN_VCC: length 5.4
  TOP w0.203: v7(18.31,27.68) 18.31,26.2 17.84,25.73 R265.1 17.84,25.31 17.82,25.29 17.82,25.06 17.8,25.03 Q21.1
  BOTTOM w0.203: U6.14 18.39,26.56 18.42,26.59 C38.1
  BOTTOM w0.381: v7(18.31,27.68) 18.42,27.58 C38.1
5V0_RS485:
  vias: v1(113.19,91.34) v1(113.68,90.54) v1(114.27,91.28)
12V_FAN_GND: length 6.3
  BOTTOM w0.381: J13.2 3.47,96.34 3.52,96.4 C209.1
  BOTTOM w0.508: L9.1 3.37,101.06 C209.1
12V_FAN_PWR: length 6.2
  BOTTOM w0.381: C210.1 7.03,97.36 6.99,97.33 6.99,96.94 J13.1
  BOTTOM w0.508: L8.1 7.18,101.06 7.03,100.91 C210.1
12V_IN: length 6.4
  BOTTOM w0.203: R34.1 v8(18.6,17.93)
  BOTTOM w0.254: TP2.1 11.58,97.86 v8(11.73,97.71)
  BOTTOM w0.381: L8.2 5.98,101.93 5.94,101.97 C208.1 v6(5.94,103.65) ; 74.91,23.56 R526.1 75.47,23 ; D2.1 2.28,104.47 v6(1.88,104.06)
  vias: v1(75.28,25) v1(75.28,23.99) v1(76.55,23.99) v8(9.7,97.71) v8(9.7,96.69) v8(9.7,95.68) v8(9.7,94.66) v8(10.14,24.36) v8(10.13,22.28) v8(10.15,23.3) v8(10.71,97.71) v8(10.71,96.69) v8(10.71,95.68) v8(10.71,94.66) v8(11.15,22.28) v8(11.16,24.36) v8(11.17,23.3) v8(11.73,96.69) v8(11.73,95.68) v8(11.73,94.66) v8(12.17,24.36) v8(12.19,23.3) v8(12.16,22.28) v8(14.42,23.74) v8(14.42,22.54) v8(15.13,23.21)
12V_IN_JACK: length 104.7
  TOP w0.381: J12.1 19.28,104.54 ; J12.1 19.28,105.6 ; J12.1 19.28,103.49 ; J12.1 14.07,103.49 ; J12.1 16.68,105.6 ; J12.1 16.68,103.49 ; J12.1 14.07,105.6 ; J12.1 14.07,104.54 ; TP1.1 20.37,95.55 ; C205.1 18.95,95.55 ; C205.1 17.98,95.55 ; C205.1 18.47,96.02
  L03_SIG w0.381: 13.82,105.85 J12.1 ; J12.1 13.82,104.54 ; J12.1 16.68,105.85 ; J12.1 16.68,103.23 ; J12.1 13.82,103.23 ; J12.1 19.54,103.23 ; J12.1 19.54,104.54 ; J12.1 19.54,105.85
  L05_SIG w0.381: 16.68,103.23 J12.1 ; J12.1 19.54,104.54 ; J12.1 13.82,103.23 ; J12.1 19.54,105.85 ; J12.1 13.82,104.54 ; J12.1 19.54,103.23 ; J12.1 13.82,105.85 ; J12.1 16.68,105.85
  L12_SIG w0.381: J12.1 16.68,105.85 ; J12.1 13.82,104.54 ; J12.1 19.54,104.54 ; J12.1 19.54,105.85 ; J12.1 13.82,105.85 ; J12.1 13.82,103.23 ; J12.1 16.68,103.23 ; J12.1 19.54,103.23
  BOTTOM w0.381: 14.07,104.54 J12.1 ; J12.1 16.68,103.49 ; J12.1 14.07,105.6 ; J12.1 19.28,104.54 ; J12.1 14.07,103.49 ; J12.1 16.68,105.6 ; J12.1 19.28,105.6 ; J12.1 19.28,103.49 ; TP1.1 20.37,95.55 ; 16.74,95.62 R133.1 16.18,96.17
  vias: v8(15.77,102.63) v8(15.77,101.61) v8(16.78,102.63) v8(16.78,101.61) v8(17.93,102.63) v8(17.93,101.61) v8(18.33,96.31) v8(18.56,97.3) v8(18.95,102.63) v8(18.94,101.36) v8(19.4,96.15) v8(19.45,97.3) v8(19.96,101.36)
AGND1: length 3.7
  BOTTOM w0.203: Z1.2 15.91,19.98 16.45,20.51 16.45,20.94 17.19,21.69 U6.5
AGND2: length 1.3
  BOTTOM w0.178: U3.11 34.08,82.85 33.83,83.1 33.83,83.32 Z4.2
AGND3: length 1.3
  BOTTOM w0.178: U5.11 25.96,81.71 25.7,81.45 25.49,81.45 Z5.2
AGND4: length 1.5
  BOTTOM w0.178: U97.11 67.13,26.2 66.65,26.68 Z6.2
GND: length 3797.8
  TOP w0.13: JA1.D43 v4(12.65,67.89) ; JA1.B43 v4(15.19,67.89)
  TOP w0.178: U25.1 48.77,23.59 v1(48.96,23.39) ; U25.3 49.91,24.35 v1(50.49,23.77)
  TOP w0.254: JA3.A6 v4(47.71,60.82) ; v1(36.95,116.45) 36.95,117.39 J11.10 37.84,117.39 v1(37.84,116.45) ; v9(15.44,76.1) v9(14.99,76.1) ; v9(15.44,76.1) JA1.B55 ; v9(15.44,76.1) JA1.B56 ; U94.B2 109.76,104.54 v1(109.96,104.75) ; JA3.A3 v4(47.71,58.91) ; JA1.D59 v7(12.67,78.33) ; JA1.A54 v9(16.57,74.83) JA1.A53 ; JA1.A49 v9(16.57,72.29) JA1.A50 ; v9(14.03,77.37) JA1.C58 ; v9(14.03,77.37) v9(14.48,77.37) ; v9(14.03,77.37) JA1.C57 ; v9(14.03,72.29) v9(14.48,72.29) ; v9(14.03,72.29) JA1.C50 ; v9(14.03,72.29) JA1.C49 ; JA1.D52 v9(12.9,73.56) JA1.D51 ; MH10.1 47.63,36.41 v7(47.63,36.69) ; MH9.1 47.64,90.31 v7(47.65,90.32) ; Q37.2 131.14,36.65 ; C87.2 v1(52.02,6.78) ; v1(69.24,91.13) 68.7,91.68 67.8,91.68 67.39,91.26 U98.5 ; v9(15.44,73.56) v9(14.99,73.56) ; v9(15.44,73.56) JA1.B52 ; v9(15.44,73.56) JA1.B51 ; U104.9 v1(105.59,71.76) ; v7(12.73,36.8) 12.72,36.7 12.72,36.41 MH7.1 ; JA1.D55 v9(12.9,76.1) JA1.D56 ; C89.2 v1(51,6.78) ; v1(72.44,96.63) 75.7,96.63 76.06,96.26 76.06,93.78 75.85,93.57 X14.2 74.75,92.8 v1(74.49,92.54) v1(72.56,92.54) 71.65,92.54 71.28,92.92 C643.2 ; v1(72.44,96.63) 71.71,96.63 v1(71.38,96.3) C644.2 v1(69.94,95.71) ; v1(72.44,96.63) X14.4 ; JA1.B48 v9(15.44,71.02) ; v9(15.44,71.02) JA1.B47 ; v9(15.44,71.02) v9(14.99,71.02) ; U42.2 v1(4.36,10.55) ; v1(54.78,13.51) 55.11,13.18 C84.2 ; Q12.2 54.15,19.32 54.25,19.43 v1(54.61,19.43) ; JA1.A58 v9(16.57,77.37) JA1.A57 ; U102.9 v1(106.1,37.98) ; v1(30.54,25.38) 30.24,25.67 U16.1 ; MH6.1 83.36,90.06 v7(83.38,90.42) ; v1(110.87,102.38) 111.03,102.54 U94.B9 ; v1(24.05,116.45) 24.05,117.39 J11.9 24.94,117.39 v1(24.94,116.45) ; Q34.2 v1(106.12,81.23) ; JA3.A9 v4(47.71,62.72) ; U103.9 v1(106.1,54.87) ; JA1.B59 v7(15.95,78.33) ; v4(45.23,60.85) 44.86,60.54 JA3.C6 ; v9(14.03,74.83) v9(14.48,74.83) ; v9(14.03,74.83) JA1.C53 ; v9(14.03,74.83) JA1.C54 ; JA1.D47 v9(12.9,71.02) JA1.D48 ; JA3.C9 45.21,62.75 v4(45.23,62.75) ; C817.2 v1(66.44,49.18) ; Q33.2 v1(80.53,98.31) ; v1(100.77,85.85) 100.77,85.81 100.68,85.9 U101.5 ; Q31.2 v1(80.66,95.65) ; Q13.2 v1(54.88,17.48) ; v7(12.73,90.38) 12.72,90.16 12.72,90.06 MH5.1 ; v4(45.23,58.94) 45.21,58.94 JA3.C3 ; U41.3 v6(16.9,97.73) ; Q32.2 v1(106.12,83.9) ; v1(56.64,9.06) 56.35,8.78 X1.4 ; C813.2 v1(66.44,41.01) ; MH8.1 v7(83.36,36.69) ; JA3.D7 v4(43.53,60.91) ; JA3.D10 v4(43.53,62.81) ; C821.2 v1(66.44,57.48)
  TOP w0.305: JA1.D12 v4(13.47,48.78) ; JA1.D9 v4(13.47,46.87) ; JA1.C2 v4(13.51,42.11) ; JA1.B3 v4(16.01,43.06) ; JA1.D39 v4(13.47,65.92) ; JA1.C25 v4(14.29,57.01) ; JA1.B23 v4(15.19,55.19) ; JA1.C21 v4(14.29,54.47) ; JA1.D31 v4(12.65,60.27) ; JA3.D4 v4(43.53,59) ; JA3.B7 v4(46.07,60.91) ; JA1.C5 v4(13.46,43.74) ; JA1.A2 v4(16,41.83) ; JA1.C11 v4(13.46,47.55) ; JA1.C29 v4(13.46,58.98) ; JA1.B35 v4(15.19,62.81) ; JA3.B10 v4(46.07,62.81) ; JA1.A41 v4(16,66.6) ; JA1.C37 v4(14.29,64.63) ; JA1.A11 v4(16,47.55) ; JA1.C46 v4(14.29,69.8) ; JA1.B15 v4(16.01,50.68) ; JA1.C33 v4(14.29,62.09) ; JA1.B6 v4(16.01,44.97) ; JA1.B12 v4(16.01,48.78) ; JA3.B4 v4(46.07,59) ; JA1.A46 v4(17.06,70.07) ; JA1.B19 v4(15.19,52.65) ; JA1.A18 v4(16.83,52.56) ; JA1.D19 v4(12.65,52.65) ; JA1.A45 v4(16.91,69.1) ; JA1.C41 v4(13.46,66.6) ; JA1.C17 v4(13.46,51.36) ; JA3.B1 v4(46.07,57.1) ; JA1.A33 v4(16.83,62.09) ; JA1.A14 v4(16,49.45) ; JA1.D15 v4(13.47,50.68) ; JA1.C1 v4(13.51,41.5) ; JA1.B39 v4(16.01,65.92) ; JA3.D1 v4(43.53,57.1) ; JA1.D27 v4(13.47,58.3) ; JA1.A8 v4(16,45.64) ; JA1.B31 v4(15.19,60.27) ; JA1.A5 v4(16,43.74) ; JA1.B27 v4(16.01,58.3) ; JA1.A21 v4(16.83,54.47) ; JA1.C8 v4(13.46,45.64) ; JA1.C14 v4(13.46,49.45) ; JA1.D35 v4(12.65,62.81) ; JA1.A26 v4(16,57.07) ; JA1.A37 v4(16.83,64.63) ; JA1.D3 v4(13.46,43.12) ; JA1.D6 v4(13.47,44.97) ; JA1.D23 v4(12.65,55.19) ; JA1.B9 v4(16.01,46.87)
  TOP w0.381: J46.2 121.42,8.41 ; J46.2 120.16,8.86 ; J46.2 120.16,5.45 ; J46.2 121.87,7.15 ; J46.2 121.42,5.9 ; J46.2 118.9,8.41 ; J46.2 118.9,5.9 ; C808.2 69.53,61.24 v1(69.11,60.81) ; C702.2 v1(106.02,60.07) ; C793.2 v1(75.13,54.23) ; C562.2 30.78,94.81 v1(30.88,94.91) ; C751.2 90.49,21.46 ; C751.2 88.88,21.46 ; C751.2 90.75,22.27 ; C751.2 88.88,23.07 ; C751.2 89.69,21.2 ; C751.2 90.49,23.07 ; C751.2 88.62,22.27 ; C751.2 89.69,23.33 ; C379.2 v1(18.08,16.63) ; R581.2 56.24,70.6 v1(56.02,70.83) ; C727.2 v1(59.23,49.1) ; J3.5 v1(39.4,10.21) ; C794.2 v1(82.37,54.53) ; v1(68.9,36.68) 69.33,37.11 C809.2 ; R624.2 R625.2 v1(107.74,43.18) ; C816.2 v1(66.44,52.11) ; 129.76,21.11 J39.M1 ; J39.M1 129.76,22.01 ; J39.M1 131.42,20.2 ; J39.M1 129.76,20.2 ; J39.M1 133.07,20.2 ; J39.M1 131.42,22.01 ; J39.M1 133.07,21.11 ; J39.M1 133.07,22.01 ; C274.2 47.41,97.2 v1(47.92,96.69) ; 59.13,2.56 J4.6 58.21,1.31 ; C804.2 v1(72.63,63.86) ; C752.2 v1(59.16,33.46) ; C730.2 v1(59.23,56.43) ; C716.2 v1(59.23,40.93) ; C768.2 v1(84.97,15.74) ; R608.2 v1(97.2,77.11) ; C95.2 62.09,22.36 v1(62.23,22.5) ; v1(32.05,20.86) C64.2 C73.2 ; C53.2 35.44,25.99 v1(35.82,25.61) ; v1(91.77,78.66) C668.2 ; 129.76,34.61 J39.M2 ; J39.M2 133.07,35.51 ; J39.M2 131.42,33.7 ; J39.M2 129.76,35.51 ; J39.M2 133.07,33.7 ; J39.M2 131.42,35.51 ; J39.M2 133.07,34.61 ; J39.M2 129.76,33.7 ; C574.2 v1(32.63,100.51) ; J3.3 v1(41.4,10.41) ; v1(69.05,28.21) 68.66,27.82 R525.2 ; C681.2 C680.2 98.73,91.81 v1(97.86,90.94) ; C625.2 v1(59.95,98.63) ; C207.2 v1(9.6,100.53) ; J3.1 v1(43.4,10.25) ; C375.2 v1(23.67,17.32) ; v1(128.82,74.34) 128.37,73.89 U116.7 ; C635.2 v1(61.1,98.8) ; C98.2 52.46,24.45 v1(52.04,24.86) ; R679.2 v1(105.36,12.76) ; C766.2 120.23,94.53 v1(120.98,94.53) R682.2 ; C94.2 v1(68.84,19.1) ; v1(31.78,94.91) 31.97,94.73 R465.2 ; C630.2 65.69,82.94 v1(65.81,82.83) ; C176.2 29.98,100.16 v1(29.61,100.52) ; C738.2 v1(59.36,63.1) ; C720.2 v1(59.23,47.24) ; R614.2 v1(96.19,77.11) ; C753.2 v1(59.17,34.48) ; C376.2 v1(14.59,16.18) ; v1(66.93,83.04) 66.7,83.27 C638.2 ; C560.2 34.5,96.01 v1(34.69,96.21) ; C101.2 51.47,20.1 v1(51.23,19.86) ; C799.2 v1(75.13,45.28) ; v1(104.43,81.13) 103.86,81.71 C657.2 C645.2 ; J11.6 v1(33.74,113.73) ; C810.2 v1(66.44,45.35) ; J3.9 v1(35.4,9.91) ; MH1.1 134.78,2.41 v7(134.77,2.43) ; C100.2 v1(62.23,17.06) ; v1(68.64,65.75) 68.5,65.61 R735.1 ; C631.2 71.03,85.22 v1(71.27,84.98) ; C631.2 v1(71.78,85.87) ; C631.2 C622.2 C624.2 ; R557.2 R553.2 53.9,90.2 v1(53.51,89.81) ; C812.2 v1(66.44,43.95) ; C778.2 v1(79.81,15.63) ; C99.2 v1(55.86,21.82) ; v1(4.75,80.95) 4.47,80.67 SW1.1 ; C815.2 v1(66.44,56.33) ; C96.2 54.26,10.92 v1(53.92,10.59) ; R612.2 v1(95.17,77.11) ; C683.2 v1(98.22,79.4) C672.2 ; v1(58.52,80.15) 59.1,80.73 R558.2 ; C773.2 88.1,14.52 v1(87.62,14.99) ; C777.2 v1(80.66,15.62) ; v1(66.59,61.84) 66.44,62 C818.2 ; R668.2 v1(116.31,97.49) ; C823.2 v1(66.44,39.99) ; C769.2 v1(84.12,15.75) ; C558.2 34.18,98.61 v1(34.69,99.13) ; v1(92.63,92.4) 93.01,92.02 C671.2 ; C235.2 v8(15.45,100.03) ; C679.2 101.49,80.09 v1(101.65,79.93) ; C93.2 43.79,24.8 v1(43.72,24.73) ; C811.2 v1(66.44,48.16) ; C822.2 v1(66.44,37.19) ; C323.2 v1(9.83,81.12) ; v1(56.86,10.69) 56.86,11.07 R79.1 ; C272.2 50.43,97 v1(50.23,96.8) ; C717.2 v1(59.23,41.95) ; J11.14 v1(26.65,103.36) ; C677.2 R615.2 89.45,87.17 v1(89.33,87.04) ; R610.2 R609.2 v1(89.33,81.45) ; v1(2.78,67.4) 3.6,66.58 C589.2 ; C285.2 63.78,83.25 v1(64.21,82.83) ; C236.2 v1(4.75,75.23) ; C798.2 v1(82.37,72.43) ; C378.2 v1(21,17.32) ; C712.2 v1(123.67,48.63) ; C205.2 18.47,94.15 v1(18.84,93.77) ; v1(94.03,92.35) 93.9,92.22 C670.2 ; U94.A2 v1(106.12,106.08) ; C637.2 v1(71.79,90.82) ; v1(107.74,59.99) R631.2 R630.2 ; C757.2 v1(59.21,39.48) ; v1(59.14,6.03) L5.1 v1(59.99,6.9) ; SW2.1 1.39,50.39 v1(1.24,50.54) ; v1(59.17,58.72) C741.2 ; C709.2 v1(105.51,76.96) ; v1(68.64,58.32) 68.5,58.18 R733.1 ; v1(2.38,55.37) 2.69,55.68 R2.2 ; C807.2 69.53,53.81 v1(69.11,53.39) ; J11.11 v1(36.17,108.07) ; R555.2 57.12,84.96 v1(56.94,84.78) ; v1(62.17,83.04) 62.38,83.25 R552.2 ; C83.2 57.81,11.1 58.19,10.71 v1(58.85,10.71) ; C796.2 v1(82.37,63.48) ; C92.2 42.85,25.76 v1(42.2,25.11) ; R135.2 v8(16.4,100.03) ; v1(59.16,57.71) C740.2 ; C684.2 v1(89.33,83.49) ; C559.2 v1(27.2,98.11) ; R737.1 68.29,41.48 v1(68.43,41.62) ; J11.12 v1(35.43,103.36) ; v1(121.03,38.3) 121.32,38.6 C710.2 ; v1(72.67,41.62) 72.43,41.37 C805.2 ; C561.2 27.98,93.69 v1(27.33,93.03) ; v1(69.11,45.51) 69.53,45.94 C806.2 ; C591.2 v1(74.09,80.98) ; C721.2 v1(59.23,48.26) ; R554.2 v1(54.39,86.7) ; C372.2 v1(24.87,17.32) ; C377.2 v1(19.66,17.32) ; R731.1 68.5,50.31 v1(68.64,50.45) ; v1(88.31,84.5) 88.95,85.14 89.51,85.14 89.76,85.39 R613.2 ; R616.2 90.15,92.44 v1(89.96,92.63) ; C629.2 C640.2 C623.2 56.19,93.67 v1(55.99,93.87) ; v1(56.94,86.38) 57.29,86.73 C632.2 57.99,86.73 C633.2 ; v1(53.36,69.88) 53.1,70.14 C666.2 ; C800.2 v1(82.37,45.84) ; C324.2 v1(7.25,81.12) ; R636.2 R637.2 107.23,76.65 v1(107.51,76.93) ; C756.2 58.93,38.47 v1(59.2,38.2) ; C97.2 v1(60.24,13.27) ; C374.2 v1(22.33,17.32) ; C825.2 v1(66.44,32.84) ; C676.2 v1(93.14,79.4) ; C789.2 v1(72.63,48.61) ; C814.2 v1(66.44,53.52) ; C780.2 92.95,11.15 v1(93.14,10.97) ; C85.2 v1(47.93,10.27) ; v1(59.31,20.85) 59.69,20.46 C105.2 ; C739.2 v1(59.21,64.11) ; C820.2 66.44,59.86 66.57,59.99 v1(66.65,59.99) ; U116.3 128.57,71.29 v1(128.7,71.42) ; C380.2 v1(15.92,17.32) ; C728.2 v1(59.23,50.11) ; J3.11 v1(33.4,9.88) ; 51.87,1.31 J4.9 50.95,2.56 ; C667.2 v1(100.63,77.11) ; R611.2 v1(94.15,77.11) ; C592.2 67.29,80.56 v1(67.29,82) ; C682.2 v1(109.01,90.85) ; C795.2 v1(75.13,63.17) ; R556.2 v1(60.15,86.16) ; v1(104.06,90.85) 103.42,90.85 103.11,90.54 R595.2 ; C797.2 v1(75.13,72.12) ; C824.2 v1(66.44,35.78) ; C695.2 v1(106.02,43.18) ; C729.2 v1(59.23,55.41) ; v1(56,90.24) 56.22,90.02 56.76,90.02 56.78,90.04 C628.2 56.86,90.04 C636.2 ; C819.2 v1(66.44,64.5) ; J3.7 v1(37.4,9.94) ; C370.2 v1(26.65,15.03) ; C783.2 v1(104.12,15) ; C238.2 v1(14.59,17.06) ; R559.2 v1(53.6,93.75) ; C711.2 125.6,38.47 v1(125.6,38.47) ; C803.2 v1(72.63,56.17) ; U94.A9 v1(114.69,101) ; C82.2 v1(59.1,15.8) ; C627.2 v1(71.78,89.42)
  TOP w0.635: 123.66,29.71 J39.2 ; J39.2 127.83,31.46 ; J39.2 123.01,31.46 ; J39.2 127.17,29.71 ; J39.2 123.66,33.21 ; J39.2 127.17,33.21 ; J39.2 125.42,33.87
  L02_GND w0.127: J15.1 22.9,93.94 ; J15.1 23.94,91.5 ; J15.1 21.51,92.54 ; J15.1 23.94,93.58 ; J15.1 21.86,93.58 ; J15.1 22.9,91.14 ; J15.1 24.3,92.54 ; J15.1 21.86,91.5 ; 76.46,26.16 J17.1 ; J17.1 77.86,27.56 ; J17.1 76.46,28.96 ; J17.1 75.42,26.52 ; J17.1 75.42,28.6 ; J17.1 77.5,28.6 ; J17.1 77.5,26.52 ; J17.1 75.06,27.56
  L02_GND w0.381: J44.2 91.19,70.87 ; J44.2 92.08,68.78 ; J44.2 92.38,69.68 ; J44.2 90.29,70.57 ; J44.2 90.29,68.78 ; J44.2 89.99,69.68 ; J44.2 91.19,68.48 ; J44.2 92.08,70.57 ; 41.4,110.56 U44.19 ; U44.19 42.94,106.91 ; U44.19 44.49,110.56 ; U44.19 42.94,111.13 ; U44.19 40.83,109.02 ; U44.19 44.49,107.48 ; U44.19 41.4,107.48 ; U44.19 45.05,109.02 ; 110.45,112.5 J18.3 ; J18.3 112.16,114.21 ; J18.3 110.9,111.24 ; J18.3 112.16,110.79 ; J18.3 113.42,113.76 ; J18.3 113.87,112.5 ; J18.3 110.9,113.76 ; J18.3 113.42,111.24 ; 131.42,33.58 J39.M2 ; J39.M2 133.2,34.61 ; J39.M2 133.2,33.58 ; J39.M2 129.63,33.58 ; J39.M2 131.42,35.64 ; J39.M2 129.63,34.61 ; J39.M2 129.63,35.64 ; J39.M2 133.2,35.64 ; 120.16,5.32 J46.2 ; J46.2 121.51,8.5 ; J46.2 121.51,5.81 ; J46.2 118.81,5.81 ; J46.2 121.99,7.15 ; J46.2 118.81,8.5 ; J46.2 120.16,8.99 ; J46.2 118.32,7.15 ; C751.2 89.69,23.46 ; C751.2 88.79,23.16 ; C751.2 90.58,23.16 ; C751.2 89.69,21.07 ; C751.2 88.49,22.27 ; C751.2 90.58,21.37 ; C751.2 88.79,21.37 ; C751.2 90.88,22.27 ; 79.98,106.63 J24.15 ; J24.15 81.17,107.05 ; J24.15 79.98,109.85 ; J24.15 78.37,108.24 ; J24.15 78.79,107.05 ; J24.15 81.59,108.24 ; J24.15 81.17,109.43 ; 64.49,106.63 J24.16 ; J24.16 65.68,107.05 ; J24.16 63.3,109.43 ; J24.16 66.1,108.24 ; J24.16 62.88,108.24 ; J24.16 63.3,107.05 ; J24.16 64.49,109.85 ; J42.1 136.58,67.32 ; J42.1 136.58,65.86 ; J42.1 135.12,67.32 ; J42.1 133.67,65.86 ; J42.1 133.67,67.32 ; U44.22 56.08,111.13 ; U44.22 54.54,107.48 ; U44.22 57.63,107.48 ; U44.22 57.63,110.56 ; U44.22 56.08,106.91 ; U44.22 58.19,109.02 ; U44.22 53.97,109.02 ; U44.22 54.54,110.56 ; U44.21 57.57,101.85 ; U44.21 54.6,101.85 ; U44.21 54.6,104.83 ; U44.21 54.05,103.34 ; U44.21 57.57,104.83 ; U44.21 56.08,105.37 ; U44.21 56.08,101.31 ; U44.21 58.12,103.34 ; J47.3 80.82,7.15 ; J47.3 77.63,5.81 ; J47.3 77.63,8.5 ; J47.3 77.15,7.15 ; J47.3 80.33,8.5 ; J47.3 78.98,8.99 ; J47.3 80.33,5.81 ; J47.3 78.98,5.32 ; J4.6 59.13,2.69 ; J4.6 60.17,1.31 ; J4.6 58.08,2.69 ; J4.6 58.08,1.31 ; J4.6 60.17,2.69 ; 129.63,20.08 J39.M1 ; J39.M1 131.42,20.08 ; J39.M1 133.2,21.11 ; J39.M1 129.63,21.11 ; J39.M1 129.63,22.14 ; J39.M1 131.42,22.14 ; J39.M1 133.2,20.08 ; J39.M1 133.2,22.14 ; J2.9 15.62,13.73 ; J2.9 13.86,13.73 ; J2.9 13.86,11.98 ; J2.9 15.91,12.85 ; J2.9 14.74,11.68 ; J2.9 15.62,11.98 ; J2.9 14.74,14.02 ; J2.9 13.57,12.85 ; 103.54,94.31 J25.1 ; J25.1 104.88,97.46 ; J25.1 102.21,97.46 ; J25.1 103.54,97.94 ; J25.1 102.21,94.79 ; J25.1 101.73,96.13 ; J25.1 104.88,94.79 ; J25.1 105.36,96.13 ; J12.2 19.26,110.54 ; J12.2 19.26,111.98 ; J12.2 19.26,109.11 ; J12.2 14.09,109.11 ; J12.2 16.68,109.11 ; J12.2 14.09,110.54 ; J12.2 16.68,111.98 ; J12.2 14.09,111.98 ; U44.4 46.7,106.33 ; U44.4 46.7,107.71 ; U44.4 45.32,106.33 ; U44.4 46.92,107.02 ; U44.4 45.32,107.71 ; U44.4 46.01,107.93 ; U44.4 45.11,107.02 ; J4.9 52,1.31 ; J4.9 52,2.69 ; J4.9 49.9,2.69 ; J4.9 49.9,1.31 ; J4.9 50.95,2.69 ; J25.4 87.87,98.85 ; J25.4 86.53,102 ; J25.4 84.72,100.19 ; J25.4 87.87,101.52 ; J25.4 88.35,100.19 ; J25.4 85.2,98.85 ; J25.4 86.53,98.37 ; J25.4 85.2,101.52 ; J16.1 3.85,44.67 ; J16.1 1.77,42.6 ; J16.1 1.77,44.67 ; J16.1 2.81,42.24 ; J16.1 2.81,45.03 ; J16.1 1.42,43.63 ; J16.1 3.85,42.6 ; J16.1 4.21,43.63 ; 91.82,95.49 J25.P10_U ; J25.P10_U 93.89,94.6 ; J25.P10_U 93,94.31 ; J25.P10_U 94.19,95.49 ; J25.P10_U 92.12,94.6 ; J25.P10_U 93.89,96.38 ; J25.P10_U 93,96.67 ; 40.91,103.34 U44.20 ; U44.20 42.94,101.31 ; U44.20 44.43,104.83 ; U44.20 42.94,105.37 ; U44.20 41.46,101.85 ; U44.20 44.43,101.85 ; U44.20 44.98,103.34 ; U44.20 41.46,104.83 ; 52.81,3.38 J4.10 ; J4.10 53.77,4.43 ; J4.10 52.81,5.49 ; J4.10 51.85,5.49 ; J4.10 53.77,3.38 ; J4.10 51.85,4.43 ; J4.10 51.85,3.38 ; J4.10 53.77,5.49 ; J45.2 96.66,8.47 ; J45.2 95.34,5.37 ; J45.2 93.56,7.15 ; J45.2 95.34,8.94 ; J45.2 94.03,8.47 ; J45.2 96.66,5.84 ; J45.2 94.03,5.84 ; J45.2 97.13,7.15 ; 48.85,104.86 U44.7 ; U44.7 49.51,106.39 ; U44.7 50.38,105.52 ; U44.7 48.65,105.52 ; U44.7 50.18,106.19 ; U44.7 48.85,106.19 ; U44.7 50.18,104.86 ; U44.7 49.51,104.65 ; 103.54,114.37 J25.2 ; J25.2 104.88,114.85 ; J25.2 105.36,116.19 ; J25.2 103.54,118 ; J25.2 104.88,117.52 ; U44.13 46.7,103.13 ; U44.13 46.7,104.51 ; U44.13 45.32,104.51 ; U44.13 46.01,104.73 ; U44.13 45.32,103.13 ; U44.13 45.11,103.82 ; U44.13 46.92,103.82 ; J24.10 67.41,104.04 ; J24.10 67.71,104.94 ; J24.10 67.41,105.83 ; J24.10 66.52,103.74 ; J24.10 65.62,104.04 ; J24.10 65.32,104.94 ; J24.10 66.52,106.13 ; J24.10 65.62,105.83 ; U44.16 49.51,103.23 ; U44.16 48.61,102.32 ; U44.16 50.42,102.32 ; U44.16 49.51,101.42 ; U44.16 50.2,101.63 ; U44.16 48.82,103.01 ; U44.16 50.2,103.01 ; U44.16 48.82,101.63 ; J23.2 34.89,15.35 ; J23.2 33.99,15.65 ; J23.2 33.99,13.26 ; J23.2 34.89,13.56 ; J23.2 32.8,14.46 ; J23.2 33.1,13.56 ; J23.2 35.18,14.46 ; J23.2 33.1,15.35 ; J43.1 116.26,78.41 ; J43.1 114.17,77.52 ; J43.1 114.47,76.62 ; J43.1 116.56,77.52 ; J43.1 115.36,78.71 ; J43.1 116.26,76.62 ; J43.1 114.47,78.41 ; J42.6 136.21,79.64 ; J42.6 135.12,80.02 ; J42.6 133.67,78.56 ; J42.6 136.58,78.56 ; J42.6 136.21,77.48 ; J42.6 134.04,77.48 ; J42.6 134.04,79.64 ; J42.6 135.12,77.1 ; 13.57,10.31 J2.10 ; J2.10 14.74,9.14 ; J2.10 13.86,11.19 ; J2.10 15.62,11.19 ; J2.10 14.74,11.48 ; J2.10 13.86,9.44 ; J2.10 15.91,10.31 ; J2.10 15.62,9.44 ; 56.31,4.43 J4.11 ; J4.11 56.31,3.38 ; J4.11 57.26,3.38 ; J4.11 56.31,5.49 ; J4.11 57.26,5.49 ; J4.11 58.22,5.49 ; J4.11 58.22,3.38 ; J4.11 58.22,4.43 ; 96.18,96.38 J25.P10_L ; J25.P10_L 97.07,94.31 ; J25.P10_L 97.96,94.6 ; J25.P10_L 95.89,95.49 ; J25.P10_L 98.25,95.49 ; J25.P10_L 96.18,94.6 ; J25.P10_L 97.07,96.67 ; J43.2 115.36,81.25 ; J43.2 115.36,78.86 ; J43.2 116.26,79.16 ; J43.2 116.55,80.06 ; J43.2 114.47,80.95 ; J43.2 114.17,80.06 ; J43.2 114.47,79.16 ; J43.2 116.26,80.95 ; 84.72,116.19 J25.3 ; J25.3 86.53,114.37 ; J25.3 85.2,114.85 ; J25.3 86.53,118 ; J25.3 85.2,117.52
  L02_GND w0.635: J39.2 127.26,33.3 ; J39.2 125.42,34 ; J39.2 127.26,29.62 ; J39.2 123.57,29.62 ; J39.2 125.42,28.92 ; J39.2 122.88,31.46 ; J39.2 123.57,33.3 ; J39.2 127.95,31.46
  L04_GND w0.127: 21.86,93.58 J15.1 ; J15.1 23.94,91.5 ; J15.1 22.9,93.94 ; J15.1 21.86,91.5 ; J15.1 24.3,92.54 ; J15.1 21.51,92.54 ; J15.1 23.94,93.58 ; J15.1 22.9,91.14 ; J17.1 77.5,26.52 ; J17.1 77.86,27.56 ; J17.1 76.46,26.16 ; J17.1 75.42,26.52 ; J17.1 76.46,28.96 ; J17.1 77.5,28.6 ; J17.1 75.42,28.6 ; J17.1 75.06,27.56
  L04_GND w0.381: J4.9 52,1.31 ; J4.9 49.9,2.69 ; J4.9 52,2.69 ; J4.9 50.95,2.69 ; J4.9 49.9,1.31 ; 110.45,112.5 J18.3 ; J18.3 113.87,112.5 ; J18.3 112.16,114.21 ; J18.3 110.9,113.76 ; J18.3 113.42,113.76 ; J18.3 110.9,111.24 ; J18.3 113.42,111.24 ; J18.3 112.16,110.79 ; J42.6 136.58,78.56 ; J42.6 134.04,79.64 ; J42.6 134.04,77.48 ; J42.6 135.12,80.02 ; J42.6 136.21,79.64 ; J42.6 133.67,78.56 ; J42.6 135.12,77.1 ; J42.6 136.21,77.48 ; J39.M2 133.2,33.58 ; J39.M2 133.2,35.64 ; J39.M2 133.2,34.61 ; J39.M2 129.63,35.64 ; J39.M2 131.42,35.64 ; J39.M2 131.42,33.58 ; J39.M2 129.63,33.58 ; J39.M2 129.63,34.61 ; 64.49,106.63 J24.16 ; J24.16 65.68,107.05 ; J24.16 63.3,109.43 ; J24.16 63.3,107.05 ; J24.16 66.1,108.24 ; J24.16 64.49,109.85 ; J24.16 62.88,108.24 ; 129.63,22.14 J39.M1 ; J39.M1 133.2,21.11 ; J39.M1 131.42,20.08 ; J39.M1 133.2,20.08 ; J39.M1 129.63,20.08 ; J39.M1 133.2,22.14 ; J39.M1 129.63,21.11 ; J39.M1 131.42,22.14 ; J24.15 81.59,108.24 ; J24.15 81.17,109.43 ; J24.15 81.17,107.05 ; J24.15 79.98,109.85 ; J24.15 79.98,106.63 ; J24.15 78.79,107.05 ; J24.15 78.37,108.24 ; 57.26,3.38 J4.11 ; J4.11 56.31,4.43 ; J4.11 58.22,4.43 ; J4.11 57.26,5.49 ; J4.11 58.22,3.38 ; J4.11 56.31,3.38 ; J4.11 58.22,5.49 ; J4.11 56.31,5.49 ; J43.2 116.26,80.95 ; J43.2 114.47,79.16 ; J43.2 114.17,80.06 ; J43.2 116.26,79.16 ; J43.2 114.47,80.95 ; J43.2 115.36,81.25 ; J43.2 116.55,80.06 ; J43.2 115.36,78.86 ; 118.32,7.15 J46.2 ; J46.2 120.16,8.99 ; J46.2 121.51,5.81 ; J46.2 121.51,8.5 ; J46.2 118.81,5.81 ; J46.2 120.16,5.32 ; J46.2 121.99,7.15 ; J46.2 118.81,8.5 ; 14.74,9.14 J2.10 ; J2.10 13.86,11.19 ; J2.10 13.86,9.44 ; J2.10 13.57,10.31 ; J2.10 15.62,11.19 ; J2.10 14.74,11.48 ; J2.10 15.91,10.31 ; J2.10 15.62,9.44 ; J45.2 97.13,7.15 ; J45.2 93.56,7.15 ; J45.2 94.03,8.47 ; J45.2 96.66,5.84 ; J45.2 95.34,5.37 ; J45.2 94.03,5.84 ; J45.2 96.66,8.47 ; J45.2 95.34,8.94 ; 114.17,77.52 J43.1 ; J43.1 116.26,76.62 ; J43.1 114.47,78.41 ; J43.1 114.47,76.62 ; J43.1 115.36,78.71 ; J43.1 115.36,76.32 ; J43.1 116.56,77.52 ; J43.1 116.26,78.41 ; J16.1 3.85,42.6 ; J16.1 1.77,44.67 ; J16.1 3.85,44.67 ; J16.1 1.77,42.6 ; J16.1 2.81,42.24 ; J16.1 2.81,45.03 ; J16.1 4.21,43.63 ; J16.1 1.42,43.63 ; J23.2 34.89,13.56 ; J23.2 33.1,15.35 ; J23.2 35.18,14.46 ; J23.2 33.99,15.65 ; J23.2 33.1,13.56 ; J23.2 33.99,13.26 ; J23.2 32.8,14.46 ; J23.2 34.89,15.35 ; 89.69,21.07 C751.2 ; C751.2 89.69,23.46 ; C751.2 90.88,22.27 ; C751.2 88.79,23.16 ; C751.2 88.79,21.37 ; C751.2 90.58,23.16 ; C751.2 88.49,22.27 ; C751.2 90.58,21.37 ; J24.10 67.41,105.83 ; J24.10 67.41,104.04 ; J24.10 66.52,103.74 ; J24.10 65.32,104.94 ; J24.10 65.62,105.83 ; J24.10 65.62,104.04 ; J24.10 67.71,104.94 ; J24.10 66.52,106.13 ; 48.82,101.63 U44.16 ; U44.16 49.51,103.23 ; U44.16 48.82,103.01 ; U44.16 50.2,101.63 ; U44.16 50.42,102.32 ; U44.16 49.51,101.42 ; U44.16 48.61,102.32 ; U44.16 50.2,103.01 ; 58.08,2.69 J4.6 ; J4.6 58.08,1.31 ; J4.6 59.13,2.69 ; J4.6 60.17,1.31 ; J4.6 60.17,2.69 ; 41.46,104.83 U44.20 ; U44.20 41.46,101.85 ; U44.20 42.94,105.37 ; U44.20 44.98,103.34 ; U44.20 44.43,101.85 ; U44.20 40.91,103.34 ; U44.20 44.43,104.83 ; U44.20 42.94,101.31 ; J25.1 104.88,94.79 ; J25.1 105.36,96.13 ; J25.1 101.73,96.13 ; J25.1 104.88,97.46 ; J25.1 103.54,94.31 ; J25.1 103.54,97.94 ; J25.1 102.21,94.79 ; J25.1 102.21,97.46 ; 52.81,3.38 J4.10 ; J4.10 53.77,3.38 ; J4.10 53.77,5.49 ; J4.10 51.85,3.38 ; J4.10 53.77,4.43 ; J4.10 52.81,5.49 ; J4.10 51.85,5.49 ; J4.10 51.85,4.43 ; U44.21 56.08,105.37 ; U44.21 57.57,101.85 ; U44.21 54.6,104.83 ; U44.21 54.05,103.34 ; U44.21 54.6,101.85 ; U44.21 58.12,103.34 ; U44.21 56.08,101.31 ; U44.21 57.57,104.83 ; J25.P10_L 97.07,96.67 ; J25.P10_L 96.18,96.38 ; J25.P10_L 98.25,95.49 ; J25.P10_L 97.96,94.6 ; J25.P10_L 95.89,95.49 ; J25.P10_L 97.07,94.31 ; J25.P10_L 96.18,94.6 ; 13.57,12.85 J2.9 ; J2.9 13.86,11.98 ; J2.9 14.74,11.68 ; J2.9 14.74,14.02 ; J2.9 15.91,12.85 ; J2.9 15.62,11.98 ; J2.9 13.86,13.73 ; J2.9 15.62,13.73 ; 90.29,70.57 J44.2 ; J44.2 90.29,68.78 ; J44.2 92.08,70.57 ; J44.2 91.19,70.87 ; J44.2 89.99,69.68 ; J44.2 92.38,69.68 ; J44.2 92.08,68.78 ; J44.2 91.19,68.48 ; J25.4 86.53,102 ; J25.4 88.35,100.19 ; J25.4 87.87,98.85 ; J25.4 84.72,100.19 ; J25.4 86.53,98.37 ; J25.4 87.87,101.52 ; J25.4 85.2,101.52 ; J25.4 85.2,98.85 ; 78.98,5.32 J47.3 ; J47.3 77.63,5.81 ; J47.3 77.15,7.15 ; J47.3 80.33,8.5 ; J47.3 80.33,5.81 ; J47.3 80.82,7.15 ; J47.3 77.63,8.5 ; J47.3 78.98,8.99 ; J12.2 19.26,110.54 ; J12.2 19.26,109.11 ; J12.2 14.09,110.54 ; J12.2 16.68,111.98 ; J12.2 16.68,109.11 ; J12.2 14.09,111.98 ; J12.2 14.09,109.11 ; J12.2 19.26,111.98 ; U44.13 46.7,103.13 ; U44.13 45.11,103.82 ; U44.13 45.32,104.51 ; U44.13 46.7,104.51 ; U44.13 46.92,103.82 ; U44.13 46.01,104.73 ; U44.13 45.32,103.13 ; 103.54,114.37 J25.2 ; J25.2 103.54,118 ; J25.2 105.36,116.19 ; J25.2 104.88,114.85 ; J25.2 104.88,117.52 ; 42.94,106.91 U44.19 ; U44.19 44.49,107.48 ; U44.19 44.49,110.56 ; U44.19 45.05,109.02 ; U44.19 41.4,110.56 ; U44.19 40.83,109.02 ; U44.19 42.94,111.13 ; U44.19 41.4,107.48 ; 53.97,109.02 U44.22 ; U44.22 57.63,107.48 ; U44.22 56.08,106.91 ; U44.22 56.08,111.13 ; U44.22 54.54,107.48 ; U44.22 54.54,110.56 ; U44.22 58.19,109.02 ; U44.22 57.63,110.56 ; U44.7 50.18,106.19 ; U44.7 48.65,105.52 ; U44.7 48.85,106.19 ; U44.7 49.51,104.65 ; U44.7 48.85,104.86 ; U44.7 50.18,104.86 ; U44.7 50.38,105.52 ; U44.7 49.51,106.39 ; 135.12,64.4 J42.1 ; J42.1 133.67,65.86 ; J42.1 136.58,67.32 ; J42.1 133.67,64.4 ; J42.1 133.67,67.32 ; J42.1 136.58,65.86 ; J42.1 136.58,64.4 ; J42.1 135.12,67.32 ; 45.32,106.33 U44.4 ; U44.4 46.7,107.71 ; U44.4 45.32,107.71 ; U44.4 45.11,107.02 ; U44.4 46.92,107.02 ; U44.4 46.7,106.33 ; U44.4 46.01,107.93 ; 85.2,114.85 J25.3 ; J25.3 84.72,116.19 ; J25.3 85.2,117.52 ; J25.3 86.53,118 ; J25.3 86.53,114.37 ; 92.12,94.6 J25.P10_U ; J25.P10_U 93.89,94.6 ; J25.P10_U 91.82,95.49 ; J25.P10_U 93,94.31 ; J25.P10_U 93.89,96.38 ; J25.P10_U 94.19,95.49 ; J25.P10_U 93,96.67
  L04_GND w0.635: 123.57,29.62 J39.2 ; J39.2 127.26,29.62 ; J39.2 125.42,28.92 ; J39.2 122.88,31.46 ; J39.2 127.95,31.46 ; J39.2 123.57,33.3 ; J39.2 127.26,33.3 ; J39.2 125.42,34
  L05_SIG w0.381: J39.M2 131.42,35.51 ; J39.M2 129.76,34.61 ; J39.M2 131.42,33.7 ; J39.M2 129.76,33.7 ; J39.M2 129.76,35.51 ; 90.38,68.87 J44.2 ; J44.2 91.99,68.87 ; J44.2 91.19,68.61
  L05_SIG w0.635: 123.66,33.21 J39.2 ; J39.2 123.01,31.46 ; J39.2 125.42,33.87 ; J39.2 127.17,29.71 ; J39.2 127.17,33.21 ; J39.2 123.66,29.71 ; J39.2 127.83,31.46
  L06_GND w0.127: 21.86,91.5 J15.1 ; J15.1 22.9,91.14 ; J15.1 21.51,92.54 ; J15.1 24.3,92.54 ; J15.1 21.86,93.58 ; J15.1 23.94,91.5 ; J15.1 22.9,93.94 ; J15.1 23.94,93.58 ; J17.1 77.86,27.56 ; J17.1 75.42,26.52 ; J17.1 75.42,28.6 ; J17.1 75.06,27.56 ; J17.1 76.46,28.96 ; J17.1 77.5,26.52 ; J17.1 77.5,28.6 ; J17.1 76.46,26.16
  L06_GND w0.381: 42.94,106.91 U44.19 ; U44.19 44.49,110.56 ; U44.19 41.4,110.56 ; U44.19 42.94,111.13 ; U44.19 45.05,109.02 ; U44.19 40.83,109.02 ; U44.19 44.49,107.48 ; U44.19 41.4,107.48 ; J4.10 53.77,5.49 ; J4.10 51.85,5.49 ; J4.10 53.77,4.43 ; J4.10 52.81,3.38 ; J4.10 53.77,3.38 ; J4.10 51.85,4.43 ; J4.10 52.81,5.49 ; J4.10 51.85,3.38 ; 89.99,69.68 J44.2 ; J44.2 91.19,70.87 ; J44.2 92.08,68.78 ; J44.2 90.29,68.78 ; J44.2 92.38,69.68 ; J44.2 90.29,70.57 ; J44.2 91.19,68.48 ; J44.2 92.08,70.57 ; 85.2,98.85 J25.4 ; J25.4 86.53,98.37 ; J25.4 88.35,100.19 ; J25.4 87.87,98.85 ; J25.4 87.87,101.52 ; J25.4 86.53,102 ; J25.4 85.2,101.52 ; J25.4 84.72,100.19 ; J2.9 15.62,11.98 ; J2.9 13.57,12.85 ; J2.9 15.62,13.73 ; J2.9 13.86,13.73 ; J2.9 14.74,14.02 ; J2.9 15.91,12.85 ; J2.9 13.86,11.98 ; J2.9 14.74,11.68 ; 14.09,110.54 J12.2 ; J12.2 16.68,111.98 ; J12.2 14.09,109.11 ; J12.2 19.26,110.54 ; J12.2 14.09,111.98 ; J12.2 16.68,109.11 ; J12.2 19.26,109.11 ; J12.2 19.26,111.98 ; 85.2,117.52 J25.3 ; J25.3 85.2,114.85 ; J25.3 86.53,118 ; J25.3 86.53,114.37 ; J25.3 84.72,116.19 ; 42.94,101.31 U44.20 ; U44.20 41.46,101.85 ; U44.20 44.43,104.83 ; U44.20 40.91,103.34 ; U44.20 41.46,104.83 ; U44.20 44.43,101.85 ; U44.20 44.98,103.34 ; U44.20 42.94,105.37 ; 133.67,65.86 J42.1 ; J42.1 135.12,64.4 ; J42.1 136.58,67.32 ; J42.1 136.58,64.4 ; J42.1 136.58,65.86 ; J42.1 135.12,67.32 ; J42.1 133.67,64.4 ; J42.1 133.67,67.32 ; 129.63,34.61 J39.M2 ; J39.M2 131.42,35.64 ; J39.M2 133.2,33.58 ; J39.M2 131.42,33.58 ; J39.M2 133.2,35.64 ; J39.M2 133.2,34.61 ; J39.M2 129.63,35.64 ; J39.M2 129.63,33.58 ; 110.9,113.76 J18.3 ; J18.3 113.42,113.76 ; J18.3 113.42,111.24 ; J18.3 110.45,112.5 ; J18.3 113.87,112.5 ; J18.3 110.9,111.24 ; J18.3 112.16,110.79 ; J18.3 112.16,114.21 ; 102.21,97.46 J25.1 ; J25.1 103.54,97.94 ; J25.1 104.88,94.79 ; J25.1 102.21,94.79 ; J25.1 105.36,96.13 ; J25.1 101.73,96.13 ; J25.1 104.88,97.46 ; J25.1 103.54,94.31 ; 54.54,110.56 U44.22 ; U44.22 56.08,106.91 ; U44.22 54.54,107.48 ; U44.22 57.63,107.48 ; U44.22 57.63,110.56 ; U44.22 58.19,109.02 ; U44.22 53.97,109.02 ; U44.22 56.08,111.13 ; J25.2 105.36,116.19 ; J25.2 103.54,114.37 ; J25.2 104.88,117.52 ; J25.2 104.88,114.85 ; J25.2 103.54,118 ; 94.03,8.47 J45.2 ; J45.2 96.66,5.84 ; J45.2 93.56,7.15 ; J45.2 97.13,7.15 ; J45.2 95.34,8.94 ; J45.2 96.66,8.47 ; J45.2 94.03,5.84 ; J45.2 95.34,5.37 ; 63.3,109.43 J24.16 ; J24.16 62.88,108.24 ; J24.16 64.49,109.85 ; J24.16 66.1,108.24 ; J24.16 65.68,107.05 ; J24.16 63.3,107.05 ; J24.16 64.49,106.63 ; 45.11,103.82 U44.13 ; U44.13 46.01,104.73 ; U44.13 45.32,103.13 ; U44.13 46.92,103.82 ; U44.13 45.32,104.51 ; U44.13 46.7,104.51 ; U44.13 46.7,103.13 ; 114.17,77.52 J43.1 ; J43.1 115.36,76.32 ; J43.1 114.47,78.41 ; J43.1 115.36,78.71 ; J43.1 116.26,78.41 ; J43.1 116.26,76.62 ; J43.1 116.56,77.52 ; J43.1 114.47,76.62 ; 65.62,104.04 J24.10 ; J24.10 67.71,104.94 ; J24.10 66.52,103.74 ; J24.10 66.52,106.13 ; J24.10 67.41,105.83 ; J24.10 65.62,105.83 ; J24.10 65.32,104.94 ; J24.10 67.41,104.04 ; 134.04,79.64 J42.6 ; J42.6 133.67,78.56 ; J42.6 134.04,77.48 ; J42.6 136.21,77.48 ; J42.6 136.21,79.64 ; J42.6 136.58,78.56 ; J42.6 135.12,80.02 ; J42.6 135.12,77.1 ; J46.2 120.16,8.99 ; J46.2 120.16,5.32 ; J46.2 118.81,8.5 ; J46.2 118.32,7.15 ; J46.2 121.51,5.81 ; J46.2 118.81,5.81 ; J46.2 121.51,8.5 ; J46.2 121.99,7.15 ; J16.1 4.21,43.63 ; J16.1 1.77,44.67 ; J16.1 1.77,42.6 ; J16.1 2.81,42.24 ; J16.1 3.85,44.67 ; J16.1 2.81,45.03 ; J16.1 3.85,42.6 ; J16.1 1.42,43.63 ; C751.2 90.58,21.37 ; C751.2 89.69,23.46 ; C751.2 88.79,21.37 ; C751.2 90.58,23.16 ; C751.2 88.79,23.16 ; C751.2 90.88,22.27 ; C751.2 88.49,22.27 ; C751.2 89.69,21.07 ; U44.7 50.38,105.52 ; U44.7 48.65,105.52 ; U44.7 48.85,104.86 ; U44.7 49.51,106.39 ; U44.7 50.18,104.86 ; U44.7 48.85,106.19 ; U44.7 49.51,104.65 ; U44.7 50.18,106.19 ; 78.37,108.24 J24.15 ; J24.15 81.17,107.05 ; J24.15 81.59,108.24 ; J24.15 79.98,106.63 ; J24.15 81.17,109.43 ; J24.15 78.79,107.05 ; J24.15 79.98,109.85 ; J39.M1 131.42,22.14 ; J39.M1 133.2,21.11 ; J39.M1 129.63,20.08 ; J39.M1 129.63,22.14 ; J39.M1 131.42,20.08 ; J39.M1 133.2,22.14 ; J39.M1 129.63,21.11 ; J39.M1 133.2,20.08 ; J2.10 15.62,11.19 ; J2.10 15.62,9.44 ; J2.10 13.86,9.44 ; J2.10 13.86,11.19 ; J2.10 13.57,10.31 ; J2.10 14.74,9.14 ; J2.10 15.91,10.31 ; J2.10 14.74,11.48 ; J47.3 80.33,8.5 ; J47.3 77.15,7.15 ; J47.3 78.98,5.32 ; J47.3 78.98,8.99 ; J47.3 77.63,5.81 ; J47.3 77.63,8.5 ; J47.3 80.33,5.81 ; J47.3 80.82,7.15 ; J43.2 115.36,81.25 ; J43.2 116.26,79.16 ; J43.2 114.47,80.95 ; J43.2 116.55,80.06 ; J43.2 116.26,80.95 ; J43.2 114.47,79.16 ; J43.2 115.36,78.86 ; J43.2 114.17,80.06 ; U44.16 50.2,101.63 ; U44.16 48.61,102.32 ; U44.16 50.42,102.32 ; U44.16 48.82,101.63 ; U44.16 50.2,103.01 ; U44.16 49.51,103.23 ; U44.16 49.51,101.42 ; U44.16 48.82,103.01 ; 49.9,1.31 J4.9 ; J4.9 49.9,2.69 ; J4.9 50.95,2.69 ; J4.9 52,1.31 ; J4.9 52,2.69 ; 32.8,14.46 J23.2 ; J23.2 33.99,13.26 ; J23.2 34.89,15.35 ; J23.2 33.1,13.56 ; J23.2 33.99,15.65 ; J23.2 34.89,13.56 ; J23.2 33.1,15.35 ; J23.2 35.18,14.46 ; J25.P10_U 93,96.67 ; J25.P10_U 93,94.31 ; J25.P10_U 93.89,94.6 ; J25.P10_U 93.89,96.38 ; J25.P10_U 91.82,95.49 ; J25.P10_U 94.19,95.49 ; J25.P10_U 92.12,94.6 ; U44.21 58.12,103.34 ; U44.21 57.57,101.85 ; U44.21 56.08,101.31 ; U44.21 57.57,104.83 ; U44.21 54.05,103.34 ; U44.21 54.6,104.83 ; U44.21 54.6,101.85 ; U44.21 56.08,105.37 ; J25.P10_L 97.07,96.67 ; J25.P10_L 95.89,95.49 ; J25.P10_L 96.18,96.38 ; J25.P10_L 97.96,94.6 ; J25.P10_L 98.25,95.49 ; J25.P10_L 97.07,94.31 ; J25.P10_L 96.18,94.6 ; 45.32,107.71 U44.4 ; U44.4 45.11,107.02 ; U44.4 46.7,107.71 ; U44.4 45.32,106.33 ; U44.4 46.7,106.33 ; U44.4 46.01,107.93 ; U44.4 46.92,107.02 ; J4.6 60.17,1.31 ; J4.6 60.17,2.69 ; J4.6 58.08,1.31 ; J4.6 58.08,2.69 ; J4.6 59.13,2.69 ; 56.31,4.43 J4.11 ; J4.11 58.22,5.49 ; J4.11 57.26,5.49 ; J4.11 58.22,3.38 ; J4.11 56.31,5.49 ; J4.11 57.26,3.38 ; J4.11 58.22,4.43 ; J4.11 56.31,3.38
  L06_GND w0.635: 125.42,28.92 J39.2 ; J39.2 122.88,31.46 ; J39.2 127.26,33.3 ; J39.2 125.42,34 ; J39.2 127.26,29.62 ; J39.2 127.95,31.46 ; J39.2 123.57,33.3 ; J39.2 123.57,29.62
  L09_GND w0.127: 75.42,28.6 J17.1 ; J17.1 77.86,27.56 ; J17.1 75.06,27.56 ; J17.1 77.5,26.52 ; J17.1 77.5,28.6 ; J17.1 75.42,26.52 ; J17.1 76.46,26.16 ; J17.1 76.46,28.96 ; 22.9,91.14 J15.1 ; J15.1 24.3,92.54 ; J15.1 22.9,93.94 ; J15.1 21.51,92.54 ; J15.1 23.94,91.5 ; J15.1 21.86,91.5 ; J15.1 23.94,93.58 ; J15.1 21.86,93.58
  L09_GND w0.381: C751.2 90.58,23.16 ; C751.2 90.88,22.27 ; C751.2 89.69,23.46 ; C751.2 90.58,21.37 ; C751.2 88.79,21.37 ; C751.2 89.69,21.07 ; C751.2 88.49,22.27 ; C751.2 88.79,23.16 ; 54.05,103.34 U44.21 ; U44.21 57.57,101.85 ; U44.21 58.12,103.34 ; U44.21 57.57,104.83 ; U44.21 56.08,105.37 ; U44.21 54.6,101.85 ; U44.21 56.08,101.31 ; U44.21 54.6,104.83 ; 135.12,77.1 J42.6 ; J42.6 133.67,78.56 ; J42.6 136.21,77.48 ; J42.6 134.04,79.64 ; J42.6 134.04,77.48 ; J42.6 136.58,78.56 ; J42.6 136.21,79.64 ; J42.6 135.12,80.02 ; 120.16,5.32 J46.2 ; J46.2 121.51,5.81 ; J46.2 118.32,7.15 ; J46.2 120.16,8.99 ; J46.2 118.81,8.5 ; J46.2 118.81,5.81 ; J46.2 121.51,8.5 ; J46.2 121.99,7.15 ; J42.1 136.58,67.32 ; J42.1 135.12,67.32 ; J42.1 135.12,64.4 ; J42.1 133.67,65.86 ; J42.1 133.67,64.4 ; J42.1 133.67,67.32 ; J42.1 136.58,65.86 ; J42.1 136.58,64.4 ; J4.10 52.81,5.49 ; J4.10 53.77,5.49 ; J4.10 53.77,3.38 ; J4.10 51.85,4.43 ; J4.10 51.85,3.38 ; J4.10 52.81,3.38 ; J4.10 53.77,4.43 ; J4.10 51.85,5.49 ; 40.91,103.34 U44.20 ; U44.20 42.94,105.37 ; U44.20 44.98,103.34 ; U44.20 41.46,104.83 ; U44.20 44.43,104.83 ; U44.20 44.43,101.85 ; U44.20 41.46,101.85 ; U44.20 42.94,101.31 ; U44.13 46.01,104.73 ; U44.13 46.7,103.13 ; U44.13 45.32,104.51 ; U44.13 46.92,103.82 ; U44.13 45.11,103.82 ; U44.13 45.32,103.13 ; U44.13 46.7,104.51 ; 13.57,10.31 J2.10 ; J2.10 13.86,11.19 ; J2.10 14.74,11.48 ; J2.10 15.91,10.31 ; J2.10 15.62,9.44 ; J2.10 13.86,9.44 ; J2.10 15.62,11.19 ; J2.10 14.74,9.14 ; U44.22 57.63,107.48 ; U44.22 53.97,109.02 ; U44.22 54.54,110.56 ; U44.22 57.63,110.56 ; U44.22 54.54,107.48 ; U44.22 56.08,111.13 ; U44.22 56.08,106.91 ; U44.22 58.19,109.02 ; J2.9 15.91,12.85 ; J2.9 15.62,11.98 ; J2.9 13.86,11.98 ; J2.9 13.57,12.85 ; J2.9 15.62,13.73 ; J2.9 14.74,11.68 ; J2.9 14.74,14.02 ; J2.9 13.86,13.73 ; 49.51,104.65 U44.7 ; U44.7 48.65,105.52 ; U44.7 49.51,106.39 ; U44.7 50.18,104.86 ; U44.7 50.38,105.52 ; U44.7 50.18,106.19 ; U44.7 48.85,106.19 ; U44.7 48.85,104.86 ; U44.19 44.49,107.48 ; U44.19 45.05,109.02 ; U44.19 41.4,107.48 ; U44.19 42.94,106.91 ; U44.19 41.4,110.56 ; U44.19 40.83,109.02 ; U44.19 44.49,110.56 ; U44.19 42.94,111.13 ; J25.1 103.54,97.94 ; J25.1 101.73,96.13 ; J25.1 102.21,94.79 ; J25.1 102.21,97.46 ; J25.1 104.88,94.79 ; J25.1 103.54,94.31 ; J25.1 105.36,96.13 ; J25.1 104.88,97.46 ; 14.09,111.98 J12.2 ; J12.2 14.09,109.11 ; J12.2 19.26,109.11 ; J12.2 19.26,110.54 ; J12.2 19.26,111.98 ; J12.2 16.68,109.11 ; J12.2 16.68,111.98 ; J12.2 14.09,110.54 ; J25.4 87.87,101.52 ; J25.4 86.53,102 ; J25.4 86.53,98.37 ; J25.4 85.2,98.85 ; J25.4 85.2,101.52 ; J25.4 88.35,100.19 ; J25.4 84.72,100.19 ; J25.4 87.87,98.85 ; J24.10 66.52,106.13 ; J24.10 65.62,104.04 ; J24.10 65.62,105.83 ; J24.10 66.52,103.74 ; J24.10 65.32,104.94 ; J24.10 67.71,104.94 ; J24.10 67.41,105.83 ; J24.10 67.41,104.04 ; J25.P10_L 97.07,96.67 ; J25.P10_L 97.96,94.6 ; J25.P10_L 95.89,95.49 ; J25.P10_L 98.25,95.49 ; J25.P10_L 96.18,96.38 ; J25.P10_L 96.18,94.6 ; J25.P10_L 97.07,94.31 ; 129.63,20.08 J39.M1 ; J39.M1 131.42,20.08 ; J39.M1 133.2,20.08 ; J39.M1 131.42,22.14 ; J39.M1 129.63,22.14 ; J39.M1 133.2,22.14 ; J39.M1 133.2,21.11 ; J39.M1 129.63,21.11 ; J45.2 97.13,7.15 ; J45.2 95.34,5.37 ; J45.2 94.03,8.47 ; J45.2 95.34,8.94 ; J45.2 94.03,5.84 ; J45.2 96.66,8.47 ; J45.2 93.56,7.15 ; J45.2 96.66,5.84 ; 103.54,114.37 J25.2 ; J25.2 104.88,117.52 ; J25.2 105.36,116.19 ; J25.2 104.88,114.85 ; J25.2 103.54,118 ; 1.42,43.63 J16.1 ; J16.1 3.85,44.67 ; J16.1 3.85,42.6 ; J16.1 2.81,42.24 ; J16.1 1.77,42.6 ; J16.1 1.77,44.67 ; J16.1 4.21,43.63 ; J16.1 2.81,45.03 ; J18.3 112.16,114.21 ; J18.3 113.42,113.76 ; J18.3 110.45,112.5 ; J18.3 113.87,112.5 ; J18.3 112.16,110.79 ; J18.3 113.42,111.24 ; J18.3 110.9,113.76 ; J18.3 110.9,111.24 ; 78.79,107.05 J24.15 ; J24.15 81.17,107.05 ; J24.15 81.17,109.43 ; J24.15 81.59,108.24 ; J24.15 79.98,106.63 ; J24.15 79.98,109.85 ; J24.15 78.37,108.24 ; 78.98,5.32 J47.3 ; J47.3 80.82,7.15 ; J47.3 80.33,5.81 ; J47.3 80.33,8.5 ; J47.3 78.98,8.99 ; J47.3 77.63,5.81 ; J47.3 77.15,7.15 ; J47.3 77.63,8.5 ; 63.3,107.05 J24.16 ; J24.16 66.1,108.24 ; J24.16 64.49,106.63 ; J24.16 64.49,109.85 ; J24.16 65.68,107.05 ; J24.16 62.88,108.24 ; J24.16 63.3,109.43 ; J4.11 58.22,5.49 ; J4.11 56.31,3.38 ; J4.11 58.22,3.38 ; J4.11 56.31,5.49 ; J4.11 57.26,5.49 ; J4.11 57.26,3.38 ; J4.11 56.31,4.43 ; J4.11 58.22,4.43 ; 32.8,14.46 J23.2 ; J23.2 33.99,15.65 ; J23.2 34.89,15.35 ; J23.2 33.1,13.56 ; J23.2 34.89,13.56 ; J23.2 35.18,14.46 ; J23.2 33.99,13.26 ; J23.2 33.1,15.35 ; U44.4 46.7,106.33 ; U44.4 45.32,107.71 ; U44.4 45.32,106.33 ; U44.4 46.7,107.71 ; U44.4 46.01,107.93 ; U44.4 46.92,107.02 ; U44.4 45.11,107.02 ; J39.M2 133.2,35.64 ; J39.M2 133.2,34.61 ; J39.M2 133.2,33.58 ; J39.M2 129.63,33.58 ; J39.M2 129.63,35.64 ; J39.M2 131.42,35.64 ; J39.M2 131.42,33.58 ; J39.M2 129.63,34.61 ; J25.P10_U 93.89,94.6 ; J25.P10_U 93,96.67 ; J25.P10_U 92.12,94.6 ; J25.P10_U 93,94.31 ; J25.P10_U 94.19,95.49 ; J25.P10_U 93.89,96.38 ; J25.P10_U 91.82,95.49 ; 58.08,2.69 J4.6 ; J4.6 60.17,1.31 ; J4.6 58.08,1.31 ; J4.6 60.17,2.69 ; J4.6 59.13,2.69 ; 85.2,117.52 J25.3 ; J25.3 86.53,118 ; J25.3 86.53,114.37 ; J25.3 85.2,114.85 ; J25.3 84.72,116.19 ; J4.9 52,2.69 ; J4.9 49.9,2.69 ; J4.9 50.95,2.69 ; J4.9 52,1.31 ; J4.9 49.9,1.31 ; 114.47,80.95 J43.2 ; J43.2 114.17,80.06 ; J43.2 116.55,80.06 ; J43.2 115.36,78.86 ; J43.2 114.47,79.16 ; J43.2 115.36,81.25 ; J43.2 116.26,79.16 ; J43.2 116.26,80.95 ; 115.36,76.32 J43.1 ; J43.1 115.36,78.71 ; J43.1 116.26,78.41 ; J43.1 114.47,78.41 ; J43.1 116.56,77.52 ; J43.1 114.47,76.62 ; J43.1 116.26,76.62 ; J43.1 114.17,77.52 ; J44.2 92.08,70.57 ; J44.2 92.38,69.68 ; J44.2 90.29,68.78 ; J44.2 91.19,70.87 ; J44.2 90.29,70.57 ; J44.2 89.99,69.68 ; J44.2 92.08,68.78 ; J44.2 91.19,68.48 ; U44.16 50.2,103.01 ; U44.16 49.51,101.42 ; U44.16 48.61,102.32 ; U44.16 49.51,103.23 ; U44.16 50.2,101.63 ; U44.16 48.82,101.63 ; U44.16 50.42,102.32 ; U44.16 48.82,103.01
  L09_GND w0.635: 125.42,28.92 J39.2 ; J39.2 122.88,31.46 ; J39.2 125.42,34 ; J39.2 123.57,29.62 ; J39.2 127.26,29.62 ; J39.2 123.57,33.3 ; J39.2 127.26,33.3 ; J39.2 127.95,31.46
  L10_SIG w0.381: J44.2 91.19,70.75 ; J44.2 90.38,68.87 ; J44.2 91.19,68.61 ; J44.2 91.99,68.87 ; J44.2 90.12,69.68 ; J44.2 91.99,70.48 ; J44.2 92.25,69.68 ; J44.2 90.38,70.48
  L11_GND w0.127: 21.86,93.58 J15.1 ; J15.1 23.94,91.5 ; J15.1 23.94,93.58 ; J15.1 21.86,91.5 ; J15.1 21.51,92.54 ; J15.1 22.9,91.14 ; J15.1 22.9,93.94 ; J15.1 24.3,92.54 ; 76.46,26.16 J17.1 ; J17.1 75.42,26.52 ; J17.1 75.06,27.56 ; J17.1 75.42,28.6 ; J17.1 76.46,28.96 ; J17.1 77.5,28.6 ; J17.1 77.86,27.56 ; J17.1 77.5,26.52
  L11_GND w0.381: J4.11 57.26,5.49 ; J4.11 56.31,5.49 ; J4.11 58.22,5.49 ; J4.11 58.22,4.43 ; J4.11 58.22,3.38 ; J4.11 57.26,3.38 ; J4.11 56.31,3.38 ; J4.11 56.31,4.43 ; 49.9,2.69 J4.9 ; J4.9 49.9,1.31 ; J4.9 50.95,2.69 ; J4.9 52,2.69 ; J4.9 52,1.31 ; 77.63,5.81 J47.3 ; J47.3 80.82,7.15 ; J47.3 78.98,8.99 ; J47.3 80.33,5.81 ; J47.3 77.15,7.15 ; J47.3 80.33,8.5 ; J47.3 78.98,5.32 ; J47.3 77.63,8.5 ; J2.9 15.62,11.98 ; J2.9 14.74,14.02 ; J2.9 13.86,13.73 ; J2.9 14.74,11.68 ; J2.9 13.57,12.85 ; J2.9 13.86,11.98 ; J2.9 15.62,13.73 ; J2.9 15.91,12.85 ; J46.2 121.99,7.15 ; J46.2 118.81,8.5 ; J46.2 118.32,7.15 ; J46.2 120.16,5.32 ; J46.2 121.51,5.81 ; J46.2 121.51,8.5 ; J46.2 118.81,5.81 ; J46.2 120.16,8.99 ; 134.04,77.48 J42.6 ; J42.6 136.21,79.64 ; J42.6 136.21,77.48 ; J42.6 134.04,79.64 ; J42.6 133.67,78.56 ; J42.6 135.12,77.1 ; J42.6 136.58,78.56 ; J42.6 135.12,80.02 ; J39.M1 131.42,22.14 ; J39.M1 131.42,20.08 ; J39.M1 133.2,22.14 ; J39.M1 133.2,20.08 ; J39.M1 129.63,20.08 ; J39.M1 129.63,21.11 ; J39.M1 133.2,21.11 ; J39.M1 129.63,22.14 ; 92.12,94.6 J25.P10_U ; J25.P10_U 91.82,95.49 ; J25.P10_U 93.89,96.38 ; J25.P10_U 94.19,95.49 ; J25.P10_U 93,96.67 ; J25.P10_U 93,94.31 ; J25.P10_U 93.89,94.6 ; J25.1 104.88,94.79 ; J25.1 104.88,97.46 ; J25.1 105.36,96.13 ; J25.1 102.21,97.46 ; J25.1 102.21,94.79 ; J25.1 103.54,97.94 ; J25.1 101.73,96.13 ; J25.1 103.54,94.31 ; U44.16 50.42,102.32 ; U44.16 48.82,103.01 ; U44.16 49.51,101.42 ; U44.16 50.2,103.01 ; U44.16 48.82,101.63 ; U44.16 48.61,102.32 ; U44.16 49.51,103.23 ; U44.16 50.2,101.63 ; U44.21 57.57,104.83 ; U44.21 54.6,101.85 ; U44.21 56.08,105.37 ; U44.21 58.12,103.34 ; U44.21 54.05,103.34 ; U44.21 54.6,104.83 ; U44.21 57.57,101.85 ; U44.21 56.08,101.31 ; 94.03,8.47 J45.2 ; J45.2 95.34,5.37 ; J45.2 96.66,8.47 ; J45.2 93.56,7.15 ; J45.2 94.03,5.84 ; J45.2 96.66,5.84 ; J45.2 97.13,7.15 ; J45.2 95.34,8.94 ; J23.2 34.89,13.56 ; J23.2 32.8,14.46 ; J23.2 35.18,14.46 ; J23.2 33.99,15.65 ; J23.2 33.1,15.35 ; J23.2 34.89,15.35 ; J23.2 33.1,13.56 ; J23.2 33.99,13.26 ; 41.4,110.56 U44.19 ; U44.19 44.49,107.48 ; U44.19 42.94,106.91 ; U44.19 40.83,109.02 ; U44.19 45.05,109.02 ; U44.19 42.94,111.13 ; U44.19 44.49,110.56 ; U44.19 41.4,107.48 ; J24.16 65.68,107.05 ; J24.16 64.49,109.85 ; J24.16 63.3,107.05 ; J24.16 64.49,106.63 ; J24.16 63.3,109.43 ; J24.16 62.88,108.24 ; J24.16 66.1,108.24 ; 88.79,21.37 C751.2 ; C751.2 89.69,23.46 ; C751.2 88.79,23.16 ; C751.2 88.49,22.27 ; C751.2 89.69,21.07 ; C751.2 90.58,21.37 ; C751.2 90.58,23.16 ; C751.2 90.88,22.27 ; 51.85,5.49 J4.10 ; J4.10 51.85,4.43 ; J4.10 53.77,3.38 ; J4.10 51.85,3.38 ; J4.10 53.77,5.49 ; J4.10 52.81,5.49 ; J4.10 52.81,3.38 ; J4.10 53.77,4.43 ; 115.36,76.32 J43.1 ; J43.1 116.26,76.62 ; J43.1 115.36,78.71 ; J43.1 116.56,77.52 ; J43.1 116.26,78.41 ; J43.1 114.47,76.62 ; J43.1 114.47,78.41 ; J43.1 114.17,77.52 ; 58.08,1.31 J4.6 ; J4.6 59.13,2.69 ; J4.6 58.08,2.69 ; J4.6 60.17,1.31 ; J4.6 60.17,2.69 ; 91.19,68.48 J44.2 ; J44.2 92.08,70.57 ; J44.2 91.19,70.87 ; J44.2 90.29,68.78 ; J44.2 92.38,69.68 ; J44.2 90.29,70.57 ; J44.2 89.99,69.68 ; J44.2 92.08,68.78 ; 42.94,101.31 U44.20 ; U44.20 41.46,104.83 ; U44.20 42.94,105.37 ; U44.20 40.91,103.34 ; U44.20 41.46,101.85 ; U44.20 44.43,101.85 ; U44.20 44.98,103.34 ; U44.20 44.43,104.83 ; J43.2 116.26,80.95 ; J43.2 114.47,79.16 ; J43.2 116.55,80.06 ; J43.2 116.26,79.16 ; J43.2 115.36,81.25 ; J43.2 115.36,78.86 ; J43.2 114.47,80.95 ; J43.2 114.17,80.06 ; J16.1 2.81,45.03 ; J16.1 1.77,42.6 ; J16.1 4.21,43.63 ; J16.1 3.85,42.6 ; J16.1 1.42,43.63 ; J16.1 2.81,42.24 ; J16.1 1.77,44.67 ; J16.1 3.85,44.67 ; U44.4 46.01,107.93 ; U44.4 46.92,107.02 ; U44.4 46.7,106.33 ; U44.4 45.32,106.33 ; U44.4 46.7,107.71 ; U44.4 45.11,107.02 ; U44.4 45.32,107.71 ; J25.4 86.53,102 ; J25.4 85.2,101.52 ; J25.4 87.87,101.52 ; J25.4 85.2,98.85 ; J25.4 84.72,100.19 ; J25.4 88.35,100.19 ; J25.4 87.87,98.85 ; J25.4 86.53,98.37 ; 14.09,109.11 J12.2 ; J12.2 16.68,109.11 ; J12.2 19.26,110.54 ; J12.2 19.26,109.11 ; J12.2 14.09,111.98 ; J12.2 19.26,111.98 ; J12.2 16.68,111.98 ; J12.2 14.09,110.54 ; 95.89,95.49 J25.P10_L ; J25.P10_L 97.96,94.6 ; J25.P10_L 98.25,95.49 ; J25.P10_L 96.18,96.38 ; J25.P10_L 97.07,94.31 ; J25.P10_L 97.07,96.67 ; J25.P10_L 96.18,94.6 ; J24.10 67.71,104.94 ; J24.10 65.32,104.94 ; J24.10 65.62,105.83 ; J24.10 67.41,104.04 ; J24.10 65.62,104.04 ; J24.10 66.52,106.13 ; J24.10 66.52,103.74 ; J24.10 67.41,105.83 ; J42.1 136.58,65.86 ; J42.1 135.12,67.32 ; J42.1 133.67,67.32 ; J42.1 135.12,64.4 ; J42.1 133.67,65.86 ; J42.1 136.58,67.32 ; J42.1 133.67,64.4 ; J42.1 136.58,64.4 ; U44.22 56.08,111.13 ; U44.22 54.54,107.48 ; U44.22 54.54,110.56 ; U44.22 57.63,107.48 ; U44.22 53.97,109.02 ; U44.22 58.19,109.02 ; U44.22 57.63,110.56 ; U44.22 56.08,106.91 ; 49.51,104.65 U44.7 ; U44.7 50.18,104.86 ; U44.7 49.51,106.39 ; U44.7 48.85,106.19 ; U44.7 48.65,105.52 ; U44.7 48.85,104.86 ; U44.7 50.18,106.19 ; U44.7 50.38,105.52 ; J25.2 105.36,116.19 ; J25.2 103.54,118 ; J25.2 104.88,117.52 ; J25.2 103.54,114.37 ; J25.2 104.88,114.85 ; 112.16,110.79 J18.3 ; J18.3 110.45,112.5 ; J18.3 113.42,113.76 ; J18.3 110.9,113.76 ; J18.3 112.16,114.21 ; J18.3 113.42,111.24 ; J18.3 110.9,111.24 ; J18.3 113.87,112.5 ; 45.11,103.82 U44.13 ; U44.13 45.32,103.13 ; U44.13 46.92,103.82 ; U44.13 46.7,104.51 ; U44.13 46.01,104.73 ; U44.13 45.32,104.51 ; U44.13 46.7,103.13 ; 14.74,9.14 J2.10 ; J2.10 13.57,10.31 ; J2.10 13.86,11.19 ; J2.10 15.91,10.31 ; J2.10 15.62,11.19 ; J2.10 15.62,9.44 ; J2.10 14.74,11.48 ; J2.10 13.86,9.44 ; J39.M2 131.42,35.64 ; J39.M2 133.2,35.64 ; J39.M2 129.63,35.64 ; J39.M2 133.2,34.61 ; J39.M2 133.2,33.58 ; J39.M2 131.42,33.58 ; J39.M2 129.63,33.58 ; J39.M2 129.63,34.61 ; J24.15 79.98,109.85 ; J24.15 78.79,107.05 ; J24.15 79.98,106.63 ; J24.15 81.59,108.24 ; J24.15 81.17,109.43 ; J24.15 81.17,107.05 ; J24.15 78.37,108.24 ; 84.72,116.19 J25.3 ; J25.3 85.2,114.85 ; J25.3 86.53,114.37 ; J25.3 86.53,118 ; J25.3 85.2,117.52
  L11_GND w0.635: 125.42,28.92 J39.2 ; J39.2 123.57,33.3 ; J39.2 127.26,33.3 ; J39.2 125.42,34 ; J39.2 127.95,31.46 ; J39.2 123.57,29.62 ; J39.2 127.26,29.62 ; J39.2 122.88,31.46
  L12_SIG w0.381: 91.19,68.61 J44.2 ; J44.2 90.12,69.68 ; J44.2 90.38,68.87
  L13_GND w0.127: 21.86,93.58 J15.1 ; J15.1 21.51,92.54 ; J15.1 23.94,91.5 ; J15.1 22.9,91.14 ; J15.1 24.3,92.54 ; J15.1 23.94,93.58 ; J15.1 22.9,93.94 ; J15.1 21.86,91.5 ; J17.1 77.5,26.52 ; J17.1 75.06,27.56 ; J17.1 77.86,27.56 ; J17.1 76.46,26.16 ; J17.1 76.46,28.96 ; J17.1 75.42,26.52 ; J17.1 75.42,28.6 ; J17.1 77.5,28.6
  L13_GND w0.381: 54.05,103.34 U44.21 ; U44.21 56.08,105.37 ; U44.21 58.12,103.34 ; U44.21 56.08,101.31 ; U44.21 54.6,101.85 ; U44.21 57.57,101.85 ; U44.21 54.6,104.83 ; U44.21 57.57,104.83 ; 114.47,76.62 J43.1 ; J43.1 114.47,78.41 ; J43.1 115.36,76.32 ; J43.1 116.26,76.62 ; J43.1 115.36,78.71 ; J43.1 114.17,77.52 ; J43.1 116.26,78.41 ; J43.1 116.56,77.52 ; 13.57,12.85 J2.9 ; J2.9 15.62,11.98 ; J2.9 14.74,14.02 ; J2.9 15.62,13.73 ; J2.9 14.74,11.68 ; J2.9 15.91,12.85 ; J2.9 13.86,11.98 ; J2.9 13.86,13.73 ; U44.4 46.7,106.33 ; U44.4 46.7,107.71 ; U44.4 46.01,107.93 ; U44.4 45.32,106.33 ; U44.4 46.92,107.02 ; U44.4 45.32,107.71 ; U44.4 45.11,107.02 ; J25.P10_L 97.07,96.67 ; J25.P10_L 98.25,95.49 ; J25.P10_L 96.18,94.6 ; J25.P10_L 96.18,96.38 ; J25.P10_L 97.07,94.31 ; J25.P10_L 97.96,94.6 ; J25.P10_L 95.89,95.49 ; 84.72,100.19 J25.4 ; J25.4 87.87,101.52 ; J25.4 86.53,98.37 ; J25.4 85.2,98.85 ; J25.4 86.53,102 ; J25.4 85.2,101.52 ; J25.4 87.87,98.85 ; J25.4 88.35,100.19 ; 41.4,110.56 U44.19 ; U44.19 41.4,107.48 ; U44.19 45.05,109.02 ; U44.19 40.83,109.02 ; U44.19 42.94,106.91 ; U44.19 44.49,110.56 ; U44.19 44.49,107.48 ; U44.19 42.94,111.13 ; J24.15 81.59,108.24 ; J24.15 79.98,109.85 ; J24.15 81.17,109.43 ; J24.15 78.37,108.24 ; J24.15 78.79,107.05 ; J24.15 81.17,107.05 ; J24.15 79.98,106.63 ; 1.42,43.63 J16.1 ; J16.1 4.21,43.63 ; J16.1 2.81,42.24 ; J16.1 2.81,45.03 ; J16.1 1.77,44.67 ; J16.1 3.85,42.6 ; J16.1 3.85,44.67 ; J16.1 1.77,42.6 ; J4.9 52,2.69 ; J4.9 50.95,2.69 ; J4.9 49.9,2.69 ; J4.9 52,1.31 ; J4.9 49.9,1.31 ; 54.54,107.48 U44.22 ; U44.22 58.19,109.02 ; U44.22 56.08,106.91 ; U44.22 53.97,109.02 ; U44.22 57.63,107.48 ; U44.22 56.08,111.13 ; U44.22 54.54,110.56 ; U44.22 57.63,110.56 ; J2.10 15.62,11.19 ; J2.10 14.74,11.48 ; J2.10 13.57,10.31 ; J2.10 14.74,9.14 ; J2.10 13.86,11.19 ; J2.10 13.86,9.44 ; J2.10 15.62,9.44 ; J2.10 15.91,10.31 ; 92.12,94.6 J25.P10_U ; J25.P10_U 93,94.31 ; J25.P10_U 93.89,96.38 ; J25.P10_U 93,96.67 ; J25.P10_U 91.82,95.49 ; J25.P10_U 94.19,95.49 ; J25.P10_U 93.89,94.6 ; U44.20 44.43,101.85 ; U44.20 44.98,103.34 ; U44.20 42.94,105.37 ; U44.20 41.46,104.83 ; U44.20 42.94,101.31 ; U44.20 41.46,101.85 ; U44.20 44.43,104.83 ; U44.20 40.91,103.34 ; 133.67,78.56 J42.6 ; J42.6 135.12,77.1 ; J42.6 136.58,78.56 ; J42.6 134.04,79.64 ; J42.6 136.21,79.64 ; J42.6 135.12,80.02 ; J42.6 134.04,77.48 ; J42.6 136.21,77.48 ; J4.10 52.81,5.49 ; J4.10 53.77,3.38 ; J4.10 51.85,5.49 ; J4.10 52.81,3.38 ; J4.10 53.77,5.49 ; J4.10 51.85,4.43 ; J4.10 53.77,4.43 ; J4.10 51.85,3.38 ; 84.72,116.19 J25.3 ; J25.3 86.53,118 ; J25.3 86.53,114.37 ; J25.3 85.2,114.85 ; J25.3 85.2,117.52 ; J44.2 92.08,70.57 ; J44.2 92.08,68.78 ; J44.2 90.29,68.78 ; J44.2 89.99,69.68 ; J44.2 91.19,68.48 ; J44.2 91.19,70.87 ; J44.2 92.38,69.68 ; J44.2 90.29,70.57 ; 129.63,34.61 J39.M2 ; J39.M2 129.63,35.64 ; J39.M2 133.2,35.64 ; J39.M2 133.2,33.58 ; J39.M2 133.2,34.61 ; J39.M2 129.63,33.58 ; J39.M2 131.42,35.64 ; J39.M2 131.42,33.58 ; U44.16 49.51,103.23 ; U44.16 50.2,101.63 ; U44.16 48.82,101.63 ; U44.16 49.51,101.42 ; U44.16 50.42,102.32 ; U44.16 48.61,102.32 ; U44.16 48.82,103.01 ; U44.16 50.2,103.01 ; 14.09,109.11 J12.2 ; J12.2 16.68,111.98 ; J12.2 16.68,109.11 ; J12.2 14.09,110.54 ; J12.2 19.26,110.54 ; J12.2 19.26,109.11 ; J12.2 19.26,111.98 ; J12.2 14.09,111.98 ; J47.3 80.82,7.15 ; J47.3 77.63,8.5 ; J47.3 78.98,8.99 ; J47.3 77.15,7.15 ; J47.3 78.98,5.32 ; J47.3 77.63,5.81 ; J47.3 80.33,8.5 ; J47.3 80.33,5.81 ; J25.1 104.88,97.46 ; J25.1 102.21,94.79 ; J25.1 103.54,94.31 ; J25.1 105.36,96.13 ; J25.1 101.73,96.13 ; J25.1 102.21,97.46 ; J25.1 104.88,94.79 ; J25.1 103.54,97.94 ; J46.2 121.99,7.15 ; J46.2 118.81,5.81 ; J46.2 118.81,8.5 ; J46.2 118.32,7.15 ; J46.2 121.51,8.5 ; J46.2 120.16,8.99 ; J46.2 120.16,5.32 ; J46.2 121.51,5.81 ; 56.31,3.38 J4.11 ; J4.11 58.22,5.49 ; J4.11 58.22,4.43 ; J4.11 56.31,5.49 ; J4.11 56.31,4.43 ; J4.11 57.26,5.49 ; J4.11 58.22,3.38 ; J4.11 57.26,3.38 ; 133.67,64.4 J42.1 ; J42.1 135.12,67.32 ; J42.1 133.67,67.32 ; J42.1 135.12,64.4 ; J42.1 136.58,65.86 ; J42.1 136.58,64.4 ; J42.1 133.67,65.86 ; J42.1 136.58,67.32 ; J18.3 113.42,111.24 ; J18.3 112.16,114.21 ; J18.3 110.45,112.5 ; J18.3 113.87,112.5 ; J18.3 110.9,111.24 ; J18.3 112.16,110.79 ; J18.3 113.42,113.76 ; J18.3 110.9,113.76 ; U44.13 46.01,104.73 ; U44.13 46.7,103.13 ; U44.13 46.92,103.82 ; U44.13 45.32,103.13 ; U44.13 45.11,103.82 ; U44.13 46.7,104.51 ; U44.13 45.32,104.51 ; 58.08,1.31 J4.6 ; J4.6 60.17,2.69 ; J4.6 58.08,2.69 ; J4.6 60.17,1.31 ; J4.6 59.13,2.69 ; J43.2 116.26,79.16 ; J43.2 115.36,78.86 ; J43.2 114.47,80.95 ; J43.2 116.26,80.95 ; J43.2 114.17,80.06 ; J43.2 116.55,80.06 ; J43.2 114.47,79.16 ; J43.2 115.36,81.25 ; 65.62,104.04 J24.10 ; J24.10 65.32,104.94 ; J24.10 67.71,104.94 ; J24.10 66.52,106.13 ; J24.10 67.41,104.04 ; J24.10 67.41,105.83 ; J24.10 66.52,103.74 ; J24.10 65.62,105.83 ; J25.2 104.88,117.52 ; J25.2 105.36,116.19 ; J25.2 103.54,114.37 ; J25.2 104.88,114.85 ; J25.2 103.54,118 ; 89.69,21.07 C751.2 ; C751.2 89.69,23.46 ; C751.2 90.58,23.16 ; C751.2 90.58,21.37 ; C751.2 88.79,21.37 ; C751.2 88.79,23.16 ; C751.2 88.49,22.27 ; C751.2 90.88,22.27 ; U44.7 49.51,106.39 ; U44.7 48.65,105.52 ; U44.7 50.18,106.19 ; U44.7 48.85,106.19 ; U44.7 50.38,105.52 ; U44.7 48.85,104.86 ; U44.7 50.18,104.86 ; U44.7 49.51,104.65 ; 94.03,5.84 J45.2 ; J45.2 97.13,7.15 ; J45.2 94.03,8.47 ; J45.2 96.66,5.84 ; J45.2 93.56,7.15 ; J45.2 95.34,8.94 ; J45.2 95.34,5.37 ; J45.2 96.66,8.47 ; 33.1,15.35 J23.2 ; J23.2 35.18,14.46 ; J23.2 34.89,13.56 ; J23.2 33.99,13.26 ; J23.2 33.99,15.65 ; J23.2 34.89,15.35 ; J23.2 32.8,14.46 ; J23.2 33.1,13.56 ; J39.M1 131.42,22.14 ; J39.M1 133.2,22.14 ; J39.M1 133.2,20.08 ; J39.M1 133.2,21.11 ; J39.M1 131.42,20.08 ; J39.M1 129.63,21.11 ; J39.M1 129.63,20.08 ; J39.M1 129.63,22.14 ; 62.88,108.24 J24.16 ; J24.16 63.3,107.05 ; J24.16 64.49,106.63 ; J24.16 65.68,107.05 ; J24.16 63.3,109.43 ; J24.16 64.49,109.85 ; J24.16 66.1,108.24
  L13_GND w0.635: 122.88,31.46 J39.2 ; J39.2 123.57,33.3 ; J39.2 127.95,31.46 ; J39.2 127.26,33.3 ; J39.2 123.57,29.62 ; J39.2 127.26,29.62 ; J39.2 125.42,34 ; J39.2 125.42,28.92
  BOTTOM w0.178: v1(42.2,25.11) 42.77,25.68 U64.3 ; U64.2 43.52,24.93 v1(43.72,24.73) 43.92,24.93 U64.1 ; U22.16 39.19,30.67 v1(39.38,30.86) ; v1(40.27,26.8) 39.85,27.22 39.37,27.22 39.19,27.39 U22.5 ; U22.10 37.21,28.46 v1(36.97,28.7) 37.12,28.86 U22.11 ; Z6.1 66.35,28
  BOTTOM w0.191: v1(79.81,15.63) 80.08,15.9 U120.2 ; v1(78.84,16.06) 78.86,16.06 79.27,16.48 U120.3 ; U118.2 84.39,16.02 v1(84.12,15.75) ; v1(84.97,15.74) 84.79,15.92 U118.1 ; v1(80.66,15.62) 80.48,15.8 U120.1 ; v1(83.15,16.18) 83.17,16.18 83.59,16.6 U118.3 ; v1(81.71,16.06) 81.3,16.48 U120.10
  BOTTOM w0.203: U115.1 51.77,42.3 51.61,42.46 51.23,42.46 51.11,42.59 C755.2 ; v1(50.34,41.97) 50.42,41.9 U115.16 ; C733.2 48.45,47.98 48.57,47.86 48.95,47.86 49.11,47.7 U111.1 ; U109.1 49.11,53.76 48.95,53.92 48.57,53.92 48.45,54.04 C719.2 ; v1(47.68,53.43) 47.76,53.35 U109.16 ; U109.11 49.51,51.29 v1(49.67,51.13) 49.91,51.37 U109.10 ; U109.4 50.31,53.76 50.47,53.92 50.86,53.92 51.03,54.1 C718.2 ; v1(31.39,42.3) 31.43,42.27 U19.14 ; v1(47.68,47.37) 47.76,47.29 U111.16 ; U115.10 52.57,39.92 v1(52.33,39.67) 52.17,39.83 U115.11 ; U111.10 49.91,45.31 v1(49.67,45.07) 49.51,45.23 U111.11 ; U115.4 52.97,42.3 53.13,42.46 53.51,42.46 53.69,42.64 C754.2 ; v1(36.86,40.93) 36.72,41.07 U19.30
  BOTTOM w0.229: Q8.2 5.3,21.13 v1(6.02,21.13) ; v1(5.63,36.37) 5.3,36.37 Q22.2 ; v1(5.76,26.08) 5.35,26.49 Q17.2 ; Q10.2 v1(5.02,15.76) ; v1(5.89,18.46) 5.48,18.87 Q9.2 ; Q7.2 v1(5.66,23.31) ; Q23.2 v1(5.15,33.16)
  BOTTOM w0.254: U9.6 60.59,28.74 ; v1(82.37,72.43) 82.59,72.43 82.98,72.03 U132.6 82.98,70.32 U132.9 ; U24.35 52.36,24.55 v1(52.04,24.86) ; U127.9 75.74,52.12 U127.6 75.74,53.84 75.35,54.23 v1(75.13,54.23) ; v9(6.81,44.13) 6.81,44.24 6.56,44.49 U7.6 ; Q30.2 v1(83.53,110.58) ; v1(59.31,20.85) 59.69,20.46 U24.51 ; v1(114.6,34.97) 112.13,37.44 R761.2 112.41,39.51 112.78,39.88 Q43.2 ; U37.23 v1(46.88,75.71) ; C569.2 61.05,83.98 60.68,83.62 X13.2 61.46,82.85 61.82,82.49 61.82,80.64 61.33,80.15 v1(58.52,80.15) 58.48,80.19 X13.4 57.35,81.25 57.27,81.17 v1(57.27,81.24) 57.27,83.92 56.94,84.25 v1(56.94,84.78) 57.54,84.78 57.61,84.71 C568.2 58.37,85.21 57.99,85.59 C303.2 ; U122.6 72.27,16.38 v11(72.47,16.18) ; R648.2 119.98,58.29 v1(120.06,58.21) ; Q6.2 5.61,29.03 v1(6.02,28.62) ; v1(91.87,85.77) 92.6,85.77 92.74,85.9 U99.5 ; U82.4 v1(29.41,107.44) ; v1(82.37,54.53) 82.59,54.53 82.98,54.14 U128.6 82.98,52.42 U128.9 ; U24.1 58.86,10.72 v1(58.85,10.71) ; U13.5 2.65,85.72 v1(2.25,85.32) ; U129.9 75.74,61.06 U129.6 75.74,62.78 75.35,63.17 v1(75.13,63.17) ; v1(51.23,13.64) 51.86,13.01 U24.15 ; C829.2 v1(64.69,30.04) ; C826.2 36.71,19.08 v1(36.41,19.37) ; v1(126.59,58.87) 126.59,60.8 126.35,61.05 U136.4 ; Z4.1 33.69,84.74 ; v1(75.13,72.12) 75.35,72.12 75.74,71.73 U131.6 75.74,70.01 U131.9 ; v1(82.37,63.48) 82.59,63.48 82.98,63.09 U130.6 82.98,61.37 U130.9 ; v1(121.49,65.15) 121.49,64.2 120.31,64.2 119.98,63.87 119.98,61.96 C731.2 ; C827.2 v1(43.37,19.04) ; Q29.2 v1(57.73,115.97) ; U24.10 54.36,10.95 54,10.59 v1(53.92,10.59) ; C656.2 103.41,87.77 104.4,87.77 v1(104.82,88.18) ; D17.3 v1(124.31,83.24) ; Q44.2 113.33,43.22 v1(113.03,43.52) ; U24.5 v1(56.86,10.69) ; v1(75.13,45.28) 75.35,45.28 75.74,44.89 U133.6 75.74,43.17 U133.9 ; Q20.2 v6(1.31,107.45) ; U24.47 v1(58.36,22) ; U96.6 54.41,75.69 ; C801.2 v1(122.9,65.15) ; U24.11 53.86,13.09 v1(53.46,13.48) 53.11,13.48 52.86,13.23 U24.13 ; v1(39.96,16.43) 40.06,16.53 Q46.2 ; Z5.1 24.06,81.32 ; D19.3 v1(118.66,82.01) ; Q48.2 v1(47.13,16.47) ; C618.2 v1(122.86,72.89) ; U11.6 42,15.22 v9(41.75,14.97) ; Q19.2 v1(63.07,21.98) ; D18.3 v1(121.46,82) ; v1(32.69,22.78) 33.2,22.27 U15.4 ; Q47.2 v1(46.43,19.56) ; U12.6 63.02,75.01 ; Q45.2 v1(39.36,19.47) ; v1(132.13,71.44) D16.3 ; Z1.1 14.25,19.98 ; U15.3 33.85,22.5 v1(33.54,22.81) ; v1(82.37,45.84) 82.59,45.84 82.98,45.45 U134.6 82.98,43.73 U134.9 ; v1(132.89,16.05) 133.17,15.77 Q28.2 ; U24.25 v1(50.97,17.96) ; X6.4 v1(47.92,96.69) ; U45.1 40.52,91.67 v1(40.91,91.27) ; U15.2 v1(34.5,22.81) ; X5.4 v1(50.23,96.8) ; Q27.2 v1(122.41,69.04) ; C828.2 77.19,84.5 77.31,84.63 v1(77.44,84.63) ; Q26.2 v1(69.74,22.59) ; D15.3 v1(132,76.52) ; C75.2 37.04,40.75 v1(36.86,40.93) ; U38.28 v1(33.59,93.91) ; C275.2 v1(37.38,78.79) ; U8.6 75.65,85.67 ; C548.2 v1(35.97,47.14)
  BOTTOM w0.381: v1(56.68,60.3) 56.97,60.6 U112.12 ; U124.4 69.78,54.06 v1(69.11,53.39) ; R51.2 v1(4.54,82.11) ; R223.2 25.1,19.91 ; R223.2 25.1,17.98 ; R223.2 25.89,18.94 ; R473.2 v1(6.9,38.09) ; J39.M2 131.42,35.51 ; J39.M2 133.07,33.7 ; J39.M2 133.07,35.51 ; J39.M2 133.07,34.61 ; J39.M2 129.76,35.51 ; J39.M2 129.76,34.61 ; J39.M2 131.42,33.7 ; J39.M2 129.76,33.7 ; R23.2 56.91,31.21 ; R23.2 56.91,30.09 ; R23.2 57.47,30.65 ; C300.2 71.66,90.69 v1(71.79,90.82) ; J46.2 121.87,7.15 ; J46.2 120.16,5.45 ; J46.2 120.16,8.86 ; J46.2 118.45,7.15 ; J46.2 121.42,8.41 ; J46.2 118.9,8.41 ; J46.2 118.9,5.9 ; J46.2 121.42,5.9 ; C715.2 126.29,56.11 v1(126.23,56.05) 125.85,56.05 125.56,56.35 U107.4 ; J39.M1 133.07,20.2 ; J39.M1 129.76,22.01 ; J39.M1 131.42,20.2 ; J39.M1 131.42,22.01 ; J39.M1 133.07,21.11 ; J39.M1 129.76,21.11 ; J39.M1 133.07,22.01 ; J39.M1 129.76,20.2 ; C673.2 103.71,83.61 v1(103.81,83.52) ; 77.72,8.41 J47.3 ; J47.3 80.24,8.41 ; J47.3 77.27,7.15 ; J47.3 77.72,5.9 ; J47.3 80.69,7.15 ; J47.3 78.98,8.86 ; J47.3 80.24,5.9 ; J47.3 78.98,5.45 ; v1(121.03,38.3) 120.72,38.3 C723.2 ; C782.2 v1(99.14,12.37) ; U112.5 62.95,60.6 v1(62.45,60.1) ; R763.2 111.23,42.94 v1(111.13,43.05) ; C781.2 v1(99.24,15.41) ; C751.2 90.49,23.07 ; C751.2 89.69,23.33 ; C751.2 88.88,23.07 ; C751.2 90.49,21.46 ; C751.2 88.88,21.46 ; C751.2 90.75,22.27 ; C751.2 89.69,21.2 ; C751.2 88.62,22.27 ; U89.3 v1(2.78,67.4) ; U66.8 v1(44.62,96.92) ; U100.4 v1(53.35,72.34) ; C387.2 v1(1.85,11.42) ; v1(46.17,72.2) C566.2 45.6,71.5 45.29,71.19 45.29,68.67 45.55,68.42 X12.2 v1(46.44,67.37) 49.44,67.37 49.79,67.72 v1(49.79,70.02) ; v1(33.61,89.2) 33.61,90.11 32.91,90.81 C564.2 v1(31.98,91.57) 31.98,91.99 v1(31.42,92.56) ; v1(33.61,89.2) X11.4 ; v1(33.61,89.2) 33.61,86.94 33.16,86.49 30.43,86.49 30.09,86.82 X11.2 29.41,87.6 28.88,88.13 28.88,90.49 C563.2 29.19,91.83 v1(29.53,92.16) ; v8(15.45,100.03) 15.51,99.97 R134.2 ; v1(59.22,43.66) 59.18,43.61 U108.11 ; U123.4 69.78,46.19 v1(69.11,45.51) ; C354.2 7.57,78.23 v1(7.2,77.87) ; C296.2 C304.2 R539.2 71.03,95.95 v1(71.38,96.3) ; C296.2 72.25,92.85 v1(72.56,92.54) ; C296.2 C291.2 ; 57.83,73.66 R523.2 57.28,74.22 ; U113.3 110.27,27.23 v1(109.9,27.61) 110.18,27.88 U113.4 ; v1(6.8,91.18) 6.53,90.91 C50.2 ; v1(51.36,49.38) 51.03,49.05 C732.2 ; C742.2 129.32,62.72 R652.2 129.32,64.36 v1(129.8,64.84) ; U108.5 62.95,44.26 v1(62.45,43.77) ; U110.12 56.97,52.43 v1(56.68,52.14) ; R44.2 v1(20.06,40.81) ; 14.3,20.94 C40.2 ; v1(93.14,79.4) C676.2 C654.2 ; R584.2 101.88,79.7 v1(101.65,79.93) 101.84,80.13 C646.2 ; v1(69.11,60.81) 69.78,61.49 U125.4 ; C557.2 v1(33.56,111.35) ; C627.2 v1(71.78,89.42) ; C765.2 132.16,74.38 v1(132.51,74.72) ; R38.2 4.96,41.17 ; U110.5 62.95,52.43 v1(62.45,51.94) ; U14.4 v8(4.29,70.6) ; v1(49.79,70.02) 49.79,71.18 49.46,71.5 C567.2 v1(48.85,72.21) ; v1(49.79,70.02) X12.4 ; v4(13.47,48.78) 13.55,48.69 C581.2 ; v1(56.68,43.97) 56.97,44.26 U108.12 ; R462.2 v1(33.56,110.47) ; v1(123.26,36.8) 123.8,36.8 124.17,37.17 U105.4 ; R514.2 v1(107.96,98.97) ; U14.6 v8(2.99,70.6) ; U14.11 2.99,78.42 v8(3.6,79.04) 3.54,79.1 C49.2 ; C755.2 51.11,43.48 v1(50.59,43.99) ; C299.2 67.72,83.39 v1(68.09,83.02) ; v1(56.86,10.69) 57.58,9.97 57.85,9.97 59.41,8.4 X2.4 v1(60.83,7.37) 64.85,7.37 65.33,7.84 65.33,9 65.02,9.3 C104.2 v1(64.52,10.2) 64.51,10.21 63.96,10.21 63.76,10 X2.2 63.03,11.09 v1(62.65,11.47) C103.2 61.73,11.91 61.44,12.19 60.21,12.19 59.86,11.85 59.86,11.02 59.55,10.71 v1(58.85,10.71) ; C683.2 v1(98.22,79.4) ; C91.2 49.9,24.36 v1(50.49,23.77) ; R566.2 v1(89.4,89.2) ; 67.48,12.26 C785.2 68.03,12.82 ; v1(56.68,35.8) 56.97,36.09 U114.12 ; C650.2 v1(96.19,79.4) ; C758.2 116.17,42.02 R661.2 116.17,44.67 116.17,44.67 v1(116.17,45.23) ; v1(106.12,106.08) 106.12,106.08 C599.2 ; C565.2 v1(34.3,108.25) ; v1(120.64,91.43) 120.28,91.43 119.72,91.99 119.24,91.99 ; C687.2 100.83,91.67 100.69,91.81 C681.2 100.25,92.25 v1(100,92.5) 99.61,92.5 99.36,92.25 C680.2 ; v1(62.45,61.44) 62.65,61.25 U112.4 ; v1(62.45,53.31) 62.69,53.08 U110.4 ; C733.2 48.45,48.87 v1(47.93,49.38) ; v1(90.85,76.88) 91.14,77.17 C661.2 ; 16.97,27.04 C38.2 ; C38.2 17.52,27.6 ; C38.2 17.52,26.48 ; v1(92.63,92.4) 93.01,92.02 C671.2 ; v1(68.9,36.68) 69.58,37.36 U137.4 ; R261.2 3.13,105.93 v6(3.6,105.46) ; C621.2 v1(20.05,41.96) ; C209.2 v6(4.42,100.28) ; C625.2 v1(59.95,98.63) ; C719.2 48.45,54.89 48.07,55.27 v1(47.71,55.27) ; R222.2 62,83.21 v1(62.17,83.04) ; C635.2 v1(61.1,98.8) ; v1(87.83,13.78) 88.23,14.19 U119.12 90.11,14.19 v1(90.4,13.89) ; v1(53.36,69.88) 52.85,70.39 U100.1 ; v1(54.02,43.99) 53.69,43.65 C754.2 ; C598.2 111.01,102.33 110.95,102.38 v1(110.87,102.38) ; C734.2 v1(119.02,46.97) 119.02,46.3 119.17,46.15 C802.2 ; U105.2 v1(125.6,38.47) ; C344.2 v1(18.9,54.45) ; 119.24,97.07 v1(120.54,97.07) ; 25.63,78.99 R26.2 25.08,79.55 ; 66.69,72.54 R17.2 ; R17.2 66.69,73.66 ; R17.2 66.14,73.1 ; R50.2 2.64,91.92 v1(2.94,92.22) ; C642.2 v1(61.62,102.43) ; v1(104.06,90.85) 103.24,90.85 R590.2 ; C665.2 v1(85.39,93.01) ; C237.2 v1(1.88,14.07) ; C722.2 125.51,43.03 125.51,43.93 R642.2 125.51,44.08 v1(125.51,44.88) ; U108.4 62.67,44.91 v1(62.43,45.16) ; U100.3 v1(50.73,71.69) ; 31.92,83.73 R16.2 31.36,83.17 ; v1(71.27,84.98) 71.03,85.22 C631.2 ; R5.2 v1(8.51,49.51) ; v1(120.44,68.63) 120.79,68.98 C764.2 ; R262.2 v1(62.06,19.06) ; v1(126.23,57.83) 126.05,57.65 U107.2 ; v1(100.63,77.11) C667.2 R586.2 ; R263.2 v1(8.55,61.64) ; v1(26.92,91.44) 27.22,91.14 R428.2 ; v1(56.97,87.45) 57.09,87.57 C633.2 57.99,86.73 C632.2 ; R608.2 v1(97.2,77.11) ; C373.2 v1(30.15,10.52) ; U110.11 59.18,51.78 v1(59.22,51.82) ; R162.2 v1(21.26,61.51) ; v1(94.03,92.35) 93.9,92.22 C670.2 ; D21.2 72.72,12.72 ; D21.2 72.11,13.27 ; D21.2 72.11,12.16 ; U106.4 125.56,47.2 125.98,46.78 v1(126.23,46.78) ; C775.2 v1(83.21,11.13) ; C286.2 56.86,96.14 v1(56.83,96.16) R560.2 ; C694.2 R623.2 108.25,38.34 107.86,37.95 v1(107.47,37.95) ; U114.5 62.95,36.09 v1(62.45,35.6) ; U92.2 v1(67.29,82) ; R675.1 v1(83.23,13.1) ; C52.2 v1(1.87,81.94) ; C234.2 v1(12.62,93.77) ; U67.8 U67.3 v1(52.86,99.74) ; 14.7,18.5 R31.2 14.15,19.06 ; 76.92,88.79 R29.2 77.48,89.34 ; C743.2 120.06,57.51 v1(120.06,58.21) 120.72,58.21 C714.2 ; C210.2 v6(6.13,99.77) ; C763.2 128.56,68.5 v1(128.82,68.5) ; R583.2 v1(104.43,81.13) ; R41.2 v1(37.26,16.49) ; C292.2 v1(63.53,98.62) ; U112.11 59.18,59.95 v1(59.22,59.99) ; v1(59.22,35.49) 59.18,35.44 U114.11 ; C776.2 v1(83.23,14.08) ; v1(120.7,75.87) 120.9,75.66 C767.2 ; U106.2 126.18,48.5 v1(126.23,48.56) 126.42,48.38 C713.2 ; C278.1 v1(50.26,78.39) ; R611.2 v1(94.15,77.11) ; C273.2 v1(49.33,76.61) ; v1(48.96,23.39) 48.88,23.47 C90.2 ; C329.2 30.35,25.56 v1(30.54,25.38) ; U91.4 v1(70.71,81.63) ; C660.2 v1(109.01,89.84) ; C718.2 51.03,55.11 v1(51.36,55.45) ; C80.2 40.45,26.98 v1(40.27,26.8) ; C620.2 v1(126.79,68.47) ; C634.2 v1(66.83,98.66) ; D20.3 v1(102.79,10.84) ; U114.4 62.69,36.74 62.45,36.98 v1(62.45,37) ; v1(123.47,39.77) 123.47,40.36 122.38,41.44 U135.4 ; C206.2 v8(17.9,93.77) ; C102.2 v1(46.11,14.58) ; R165.2 v1(21.31,57.7) ; C600.2 v1(106.09,103.17) ; U26.5 v1(65.03,22.02) ; R213.2 v1(50.03,74.81) ; v1(132.89,16.05) 132.83,15.99 R532.2 ; C371.2 v1(27.86,12.3) ; U66.3 v1(44.62,99.34) ; C601.2 v1(118.79,99.76) ; v4(13.46,43.12) 13.31,43.12 13.03,43.4 C582.2 ; C747.2 114.74,26.33 v1(114.73,26.34) 114.48,26.58 U113.7 ; v1(76.57,25.06) 77.19,25.06 C617.2 v1(77.65,25.76) ; C369.2 v1(33.56,112.37) ; R167.2 v1(6.9,14.07) ; U14.5 v8(3.64,70.6) ; C353.2 v1(7.53,75.56) ; C51.2 v1(7.11,83.09) ; R589.2 103.11,86.03 C685.2 v1(103.83,85.39) ; Q18.2 v6(6.14,108.46) ; C678.2 C669.2 89.58,78.66 v1(89.33,78.41) ; C276.2 v1(39.98,72.25) ; R241.2 v1(36.56,24.98) ; R681.2 v1(115.25,88.89) ; R474.2 v1(4.55,34.97) ; C175.2 v1(28.42,101.29) ; C759.2 v1(116.51,27.43) ; C81.2 v1(41.98,29.79) ; R685.2 v1(76.06,15.26) ; C619.2 v1(73.29,20.91) ; C284.2 C295.2 v1(56,90.24) ; C277.2 v1(43.18,70.83) ; R163.2 v1(21.33,60.24) ; U113.2 v1(109.9,26.58)
  BOTTOM w0.635: J39.2 127.83,31.46 ; J39.2 127.17,29.71 ; J39.2 123.66,33.21 ; J39.2 123.66,29.71 ; J39.2 125.42,33.87 ; J39.2 127.17,33.21 ; J39.2 123.01,31.46
  vias: v1(1.24,55.37) v1(1.24,54.1) v1(1.24,52.83) v1(1.24,51.68) v1(1.24,49.4) v1(1.85,58.57) v1(1.85,57.43) v1(1.85,56.28) v1(2.03,62) v1(2.03,60.85) v1(2.03,59.71) v1(2.38,54.1) v1(2.38,52.83) v1(2.7,87.36) v1(3.17,62) v1(3.17,60.85) v1(3.17,59.71) v1(3.65,87.93) v1(3.65,86.78) v1(4.6,87.36) v1(23.03,97.46) v1(23.03,96.31) v1(23.16,101.14) v1(23.94,83.63) v1(23.94,82.49) v1(24.18,97.46) v1(24.45,79.28) v1(24.45,78.14) v1(24.68,101.14) v1(24.66,87.49) v1(24.66,86.48) v1(24.66,85.46) v1(25.28,93.6) v1(29.08,98.51) v1(29.08,97.61) v1(29.08,96.71) v1(29.08,95.81) v1(29.08,94.91) v1(29.98,98.51) v1(29.98,97.61) v1(29.98,96.71) v1(29.98,95.81) v1(29.98,94.91) v1(30.51,84.36) v1(30.88,98.51) v1(30.88,97.61) v1(30.88,96.71) v1(30.88,95.81) v1(31.66,84.36) v1(31.78,98.51) v1(31.78,97.61) v1(31.78,96.71) v1(31.78,95.81) v1(32.68,98.51) v1(32.68,97.61) v1(32.68,96.71) v1(32.68,95.81) v1(32.68,94.91) v1(33.35,42.4) v1(33.35,40.93) v1(34.83,42.4) v1(34.83,40.93) v1(34.86,84.86) v1(36.01,84.86) v1(37.84,84.15) v1(38.79,95.27) v1(38.79,94.27) v1(38.85,84.15) v1(39.54,94.77) v1(39.87,84.15) v1(40.29,95.27) v1(40.29,94.27) v1(41.19,13.53) v1(41.47,94.3) v1(42.06,13.47) v1(42.42,78.16) v1(42.42,77.36) v1(42.42,76.56) v1(42.42,75.76) v1(42.69,95.23) v1(43.05,97.04) v1(43.22,78.16) v1(43.22,77.36) v1(43.22,76.56) v1(43.22,75.76) v1(44.02,78.16) v1(44.02,77.36) v1(44.02,76.56) v1(44.02,75.76) v1(44.82,78.16) v1(44.82,77.36) v1(44.82,76.56) v1(44.82,75.76) v1(46.07,96.44) v1(46.16,81.49) v1(46.35,100.58) v1(48.33,100.33) v1(48.5,81.49) v1(50.85,94.92) v1(50.92,99.84) v1(52.17,93.11) v1(52.83,94.94) v1(54.15,77.34) v1(54.66,95.04) v1(55.17,77.34) v1(55.6,5.96) v1(55.91,86.83) v1(57.02,74.26) v1(57.71,30.67) v1(58.09,98.57) v1(59.03,98.6) v1(59.57,27.14) v1(60.59,27.14) v1(63.02,76.61) v1(63.47,101.88) v1(64.03,76.61) v1(64.53,28.11) v1(64.92,101.88) v1(65.02,100.2) v1(65.59,86.2) v1(65.67,28.11) v1(65.9,73.08) v1(67.48,12.07) v1(67.67,98.68) v1(67.91,28.21) v1(70.93,27.73) v1(71.95,27.73) v1(72.11,11.97) v1(72.38,18.18) v1(72.96,27.73) v1(73.4,18.18) v1(73.68,38.31) v1(73.89,86.71) v1(73.88,85.75) v1(73.86,56.49) v1(73.98,27.73) v1(77.58,88.55) v1(78.33,70.79) v1(78.41,63.67) v1(78.41,55.16) v1(78.43,49.37) v1(78.58,72.28) v1(79.24,53.87) v1(79.83,56.61) v1(79.93,62.78) v1(80.23,49.4) v1(80.34,47.93) v1(80.69,65.58) v1(80.82,57.96) v1(81.45,55.8) v1(82.09,64.82) v1(82.98,57.32) v1(84.37,66.34) v1(84.74,47.22) v1(85.19,70.73) v1(85.26,44.12) v1(85.39,61.64) v1(85.64,63.67) v1(85.64,54.78) v1(85.64,52.62) v1(85.77,72.31) v1(85.77,57.32) v1(85.77,45.89) v1(86.15,48.18) v1(86.28,64.44) v1(86.66,69.39) v1(86.66,55.8) v1(86.91,53.51) v1(87.17,65.58) v1(87.3,50.97) v1(87.42,61.77) v1(87.55,46.91) v1(87.68,45) v1(87.68,43.48) v1(87.8,70.28) v1(87.8,59.1) v1(87.93,66.47) v1(88.21,57.3) v1(88.57,51.99) v1(89.2,67.61) v1(89.58,50.47) v1(89.84,63.42) v1(89.84,61.9) v1(89.84,59.61) v1(89.84,57.32) v1(89.84,55.8) v1(89.91,53.74) v1(89.91,52.73) v1(89.91,45) v1(89.91,43.48) v1(89.91,42.34) v1(89.91,41.07) v1(89.91,39.8) v1(89.91,38.53) v1(89.91,37.26) v1(89.91,35.99) v1(89.91,34.72) v1(89.91,33.45) v1(89.91,32.18) v1(89.91,30.91) v1(89.91,29.64) v1(89.96,48.18) v1(89.96,46.78) v1(90.09,64.44) v1(90.85,50.21) v1(90.98,42.72) v1(91.18,13.45) v1(91.74,19.45) v1(91.74,18.18) v1(92.07,13.45) v1(92.5,63.04) v1(92.5,60.75) v1(92.5,59.1) v1(92.5,56.82) v1(92.48,53.51) v1(92.5,48.43) v1(92.57,83.4) v1(92.76,50.34) v1(92.76,43.1) v1(92.88,40.81) v1(93.01,19.45) v1(93.01,18.18) v1(92.99,13.45) v1(93.52,65.88) v1(93.52,64.44) v1(93.65,46.78) v1(93.77,45.26) v1(93.77,39.92) v1(93.9,61.51) v1(93.9,59.1) v1(93.9,57.7) v1(93.9,55.42) v1(93.87,54.28) v1(93.87,52.12) v1(93.9,49.2) v1(93.9,43.73) v1(94.53,19.45) v1(94.53,18.18) v1(95.81,90.91) v1(95.8,19.45) v1(95.8,18.18) v1(96.19,92.87) v1(97.07,65.88) v1(97.17,92.83) v1(97.2,18.44) v1(97.2,17.17) v1(98.22,64.31) v1(98.47,18.44) v1(98.47,17.17) v1(99.61,60.24) v1(99.64,49.42) v1(99.69,64.97) v1(99.74,18.44) v1(99.74,17.17) v1(100.78,65.43) v1(101.01,18.44) v1(101.01,17.17) v1(101.14,60.37) v1(101.62,55.47) v1(101.75,67.13) v1(101.9,54.66) v1(101.93,37.66) v1(101.93,36.11) v1(102.28,18.44) v1(102.28,17.17) v1(102.51,41.75) v1(102.7,72.38) v1(102.79,57.2) v1(102.79,14.8) v1(103.17,55.39) v1(103.21,38.6) v1(103.55,18.44) v1(103.55,17.17) v1(104.06,57.83) v1(104.32,71.76) v1(104.42,48.38) v1(104.85,67) v1(104.83,54.87) v1(104.83,37.98) v1(104.82,18.44) v1(104.82,17.17) v1(104.9,65.53) v1(105.2,40.31) v1(105.2,35.99) v1(105.33,59.23) v1(105.69,53.01) v1(106.09,18.44) v1(106.35,37) v1(107.13,48.33) v1(107.13,36.17) v1(107.36,18.44) v1(107.49,53.26) v1(108.16,55.29) v1(108.63,18.44) v1(109.13,16.2) v1(109.13,14.93) v1(109.86,16.84) v1(109.86,15.57) v1(109.86,14.3) v1(109.98,78.19) v1(109.98,77.3) v1(110.15,18.41) v1(110.41,50.24) v1(110.49,61.3) v1(110.49,60.41) v1(110.49,44.41) v1(110.49,43.52) v1(110.53,16.2) v1(110.53,14.93) v1(110.61,89.39) v1(110.62,76.83) v1(111.13,59.94) v1(111.13,16.84) v1(111.13,15.57) v1(111.13,14.3) v1(111.25,78.19) v1(111.25,77.3) v1(111.54,88.56) v1(111.76,61.3) v1(111.76,60.41) v1(111.76,44.41) v1(111.76,43.52) v1(111.89,76.83) v1(112.02,16.84) v1(112.02,15.57) v1(112.02,14.3) v1(112.24,50.39) v1(112.29,33.55) v1(112.4,59.94) v1(112.4,43.05) v1(112.52,78.19) v1(112.52,77.3) v1(113.03,61.3) v1(113.03,60.41) v1(113.03,44.41) v1(113.56,65.55) v1(113.8,45.41) v1(114.02,67) v1(114.19,48.28) v1(114.22,46.88) v1(114.25,33.52) v1(114.3,49.85) v1(114.32,40.38) v1(114.73,59.23) v1(114.85,57.83) v1(115.49,32.81) v1(115.62,30.02) v1(115.92,57.22) v1(117.01,57.83) v1(117.01,33.57) v1(117.14,34.97) v1(117.39,59.23) v1(117.39,30.02) v1(117.83,45.18) v1(118.21,47.54) v1(118.41,40.13) v1(118.51,41.73) v1(118.69,49.12) v1(118.79,35.61) v1(118.92,67) v1(118.87,65.55) v1(119.43,33.57) v1(119.58,16.81) v1(119.58,15.54) v1(119.58,14.27) v1(119.58,13) v1(120.06,39.29) v1(120.22,87.14) v1(120.85,16.81) v1(120.85,15.54) v1(120.85,14.27) v1(120.85,13) v1(121.71,36.37) v1(122.4,46.15) v1(122.62,87.14) v1(123.47,67) v1(123.99,45.25) v1(125.17,65.48) v1(125.55,97.79) v1(125.57,95.09) v1(125.78,36.5) v1(126.64,65.78) v1(127.76,64.87) v7(2.4,114) v7(2.4,5) v7(5,116.6) v7(5,111.4) v7(5,7.6) v7(5,2.4) v7(7.6,114) v7(7.6,5) v7(9.42,87.05) v7(9.42,33.4) v7(10.3,84.89) v7(10.3,35.69) v7(10.43,89.34) v7(10.43,31.12) v7(12.72,83.75) v7(12.72,30.1) v7(15,89.34) v7(15,84.77) v7(15,35.69) v7(15,31.12) v7(16.02,87.05) v7(16.02,33.28) v7(44.34,87.05) v7(44.34,33.4) v7(45.22,31.24) v7(45.35,89.34) v7(45.35,84.77) v7(45.35,35.82) v7(47.64,83.75) v7(47.64,30.1) v7(49.92,89.34) v7(49.92,84.77) v7(50.05,35.69) v7(50.05,31.12) v7(50.94,87.05) v7(50.94,33.4) v7(80.07,87.05) v7(80.07,33.4) v7(80.95,89.34) v7(80.95,84.77) v7(80.95,35.69) v7(80.95,31.12) v7(82.35,83.89) v7(83.37,30.1) v7(85.65,89.34) v7(85.78,35.69) v7(85.91,84.89) v7(85.91,31.24) v7(86.68,87.05) v7(86.67,33.4) v7(132.4,113.98) v7(132.4,5.01) v7(135,116.58) v7(135,7.61) v7(136.19,111.68) v7(137.6,113.98) v7(137.6,5.01) v8(0.94,110.41) v8(0.94,108.25) v8(0.91,90.17) v8(0.91,87.66) v8(0.91,85.17) v8(0.91,82.66) v8(0.91,80.17) v8(0.91,77.66) v8(0.91,75.17) v8(0.91,72.63) v8(0.91,70.09) v8(0.91,67.55) v8(0.91,65.01) v8(0.91,62.47) v8(0.91,59.93) v8(0.91,57.39) v8(0.91,40.17) v8(0.91,37.66) v8(0.91,35.17) v8(0.91,32.66) v8(0.91,30.17) v8(0.91,27.66) v8(0.91,25.17) v8(0.91,22.66) v8(0.91,20.17) v8(0.91,17.66) v8(0.91,10.15) v8(0.96,48.3) v8(0.96,45.79) v8(2.99,69.59) v8(3.64,69.59) v8(4.29,69.59) v8(5.16,41.37) v8(5.49,43.93) v8(5.49,43.04) v8(8.73,118) v8(8.71,0.9) v8(9.85,43.94) v8(9.85,43.05) v8(11.22,118) v8(11.2,0.9) v8(11.97,21.18) v8(11.97,20.17) v8(12.54,26.69) v8(13.23,100.98) v8(13.55,20.02) v8(13.71,118) v8(13.66,26.67) v8(13.71,0.9) v8(13.96,19.1) v8(14.16,18.02) v8(15.03,26.97) v8(15.03,25.95) v8(15.71,25.29) v8(16.2,118) v8(16.2,0.9) v8(17.4,27.73) v8(17.47,26.34) v8(18.33,29.1) v8(18.42,30.32) v8(18.71,118) v8(18.71,0.9) v8(20.51,30.47) v8(20.51,29.45) v8(21.2,118) v8(21.2,0.9) v8(22.54,30.47) v8(22.54,29.45) v8(23.23,118) v8(23.71,0.9) v8(24.57,30.47) v8(24.57,29.45) v8(26.09,19.46) v8(26.12,18.2) v8(26.2,0.9) v8(26.28,118) v8(28.74,0.9) v8(28.82,118) v8(31.36,118) v8(33.9,118) v8(36.06,118) v8(38.98,118) v8(41.44,0.9) v8(41.52,118) v8(43.98,0.9) v8(44.06,118) v8(46.52,0.9) v8(46.6,118) v8(49.14,118) v8(49.06,0.9) v8(50.59,2.97) v8(51.68,118) v8(52.24,2.08) v8(53.88,1.31) v8(54.22,118) v8(56.19,1.31) v8(56.76,118) v8(57.83,2.08) v8(59.3,118) v8(59.48,2.97) v8(61.04,0.9) v8(61.2,118) v8(62.66,92.64) v8(62.66,91.89) v8(62.66,91.14) v8(62.66,90.39) v8(63.41,92.64) v8(63.41,91.89) v8(63.41,91.14) v8(63.41,90.39) v8(63.58,0.9) v8(64.16,92.64) v8(64.16,91.89) v8(64.16,91.14) v8(64.16,90.39) v8(64.38,116.73) v8(64.91,92.64) v8(64.91,91.89) v8(64.91,91.14) v8(64.91,90.39) v8(66.12,0.9) v8(66.92,116.73) v8(68.66,0.9) v8(69.46,116.73) v8(71.2,0.9) v8(72,116.73) v8(73.71,0.9) v8(74.54,116.73) v8(76.2,0.9) v8(77.08,116.73) v8(78.71,0.9) v8(79.62,116.73) v8(81.2,0.9) v8(82.6,116.76) v8(83.74,118.03) v8(83.74,115.49) v8(83.71,0.9) v8(86.2,0.9) v8(88.71,0.9) v8(91.2,0.9) v8(93.71,0.9) v8(95.57,87.28) v8(95.57,86.53) v8(95.57,85.78) v8(95.57,85.03) v8(96.2,0.9) v8(96.32,87.28) v8(96.32,86.53) v8(96.32,85.78) v8(96.32,85.03) v8(97.07,87.28) v8(97.07,86.53) v8(97.07,85.78) v8(97.07,85.03) v8(97.82,87.28) v8(97.82,86.53) v8(97.82,85.78) v8(97.82,85.03) v8(98.71,0.9) v8(101.2,0.9) v8(103.71,0.9) v8(105.78,118) v8(105.78,115.46) v8(106.2,0.9) v8(108.32,118) v8(108.74,0.9) v8(110.86,118) v8(111.28,0.9) v8(113.4,118) v8(113.82,0.9) v8(115.94,118) v8(116.36,0.9) v8(118.48,118) v8(118.9,0.9) v8(121.02,118) v8(121.44,0.9) v8(123.56,118) v8(126.1,118) v8(128.64,118) v8(131.18,118) v8(131.6,0.9) v8(139.09,110.15) v8(139.09,107.66) v8(139.09,105.25) v8(139.09,102.71) v8(139.09,100.17) v8(139.09,97.66) v8(139.09,95.17) v8(139.09,92.66) v8(139.09,90.17) v8(139.09,87.66) v8(139.09,85.17) v8(139.09,82.66) v8(139.09,80.17) v8(139.09,77.66) v8(139.09,75.17) v8(139.09,72.66) v8(139.09,70.17) v8(139.09,67.66) v8(139.09,65.17) v8(139.09,62.66) v8(139.09,60.17) v8(139.09,57.66) v8(139.09,55.17) v8(139.09,52.66) v8(139.09,50.17) v8(139.09,42.66) v8(139.09,40.17) v8(139.09,37.66) v8(139.09,35.17) v8(139.09,32.66) v8(139.09,30.17) v8(139.09,27.66) v8(139.09,25.17) v8(139.09,22.66) v8(139.09,15.17) v8(139.09,12.66) v8(139.09,10.15) v9(6.21,44.13) v9(6.21,43.53) v9(6.21,42.93) v9(6.81,43.53) v9(6.81,42.93) v9(7.41,44.13) v9(7.41,43.53) v9(7.41,42.93) v9(11.94,77.37) v9(11.94,74.83) v9(41.15,15.57) v9(41.15,14.97) v9(41.15,14.37) v9(41.75,15.57) v9(41.75,14.37) v9(42.35,15.57) v9(42.35,14.97) v9(42.35,14.37) v10(74.99,70.36) v10(74.99,69.16) v10(74.99,61.41) v10(74.99,60.21) v10(74.99,52.47) v10(74.99,51.27) v10(74.99,43.52) v10(74.99,42.32) v10(76.99,70.36) v10(76.99,69.16) v10(76.99,61.41) v10(76.99,60.21) v10(76.99,52.47) v10(76.99,51.27) v10(76.99,43.52) v10(76.98,42.34) v10(82.23,70.67) v10(82.23,69.47) v10(82.23,61.72) v10(82.23,60.52) v10(82.23,52.77) v10(82.23,51.57) v10(82.23,44.08) v10(82.23,42.88) v10(84.23,70.67) v10(84.23,69.47) v10(84.23,61.72) v10(84.23,60.52) v10(84.23,52.77) v10(84.23,51.57) v10(84.23,44.08) v10(84.23,42.88) v10(106.49,15.52) v10(107.76,15.52) v11(54.23,76.34) v11(54.23,75.49) v11(55.03,76.34) v11(55.03,75.49) v11(59.7,28.94) v11(59.7,28.09) v11(60.5,28.94) v11(60.5,28.09) v11(63.1,75.66) v11(63.1,74.81) v11(63.9,75.66) v11(63.9,74.81) v11(72.47,17.03) v11(73.27,17.03) v11(73.27,16.18) v11(75,86.55) v11(75,85.75) v11(75.85,86.55) v11(75.85,85.75)
